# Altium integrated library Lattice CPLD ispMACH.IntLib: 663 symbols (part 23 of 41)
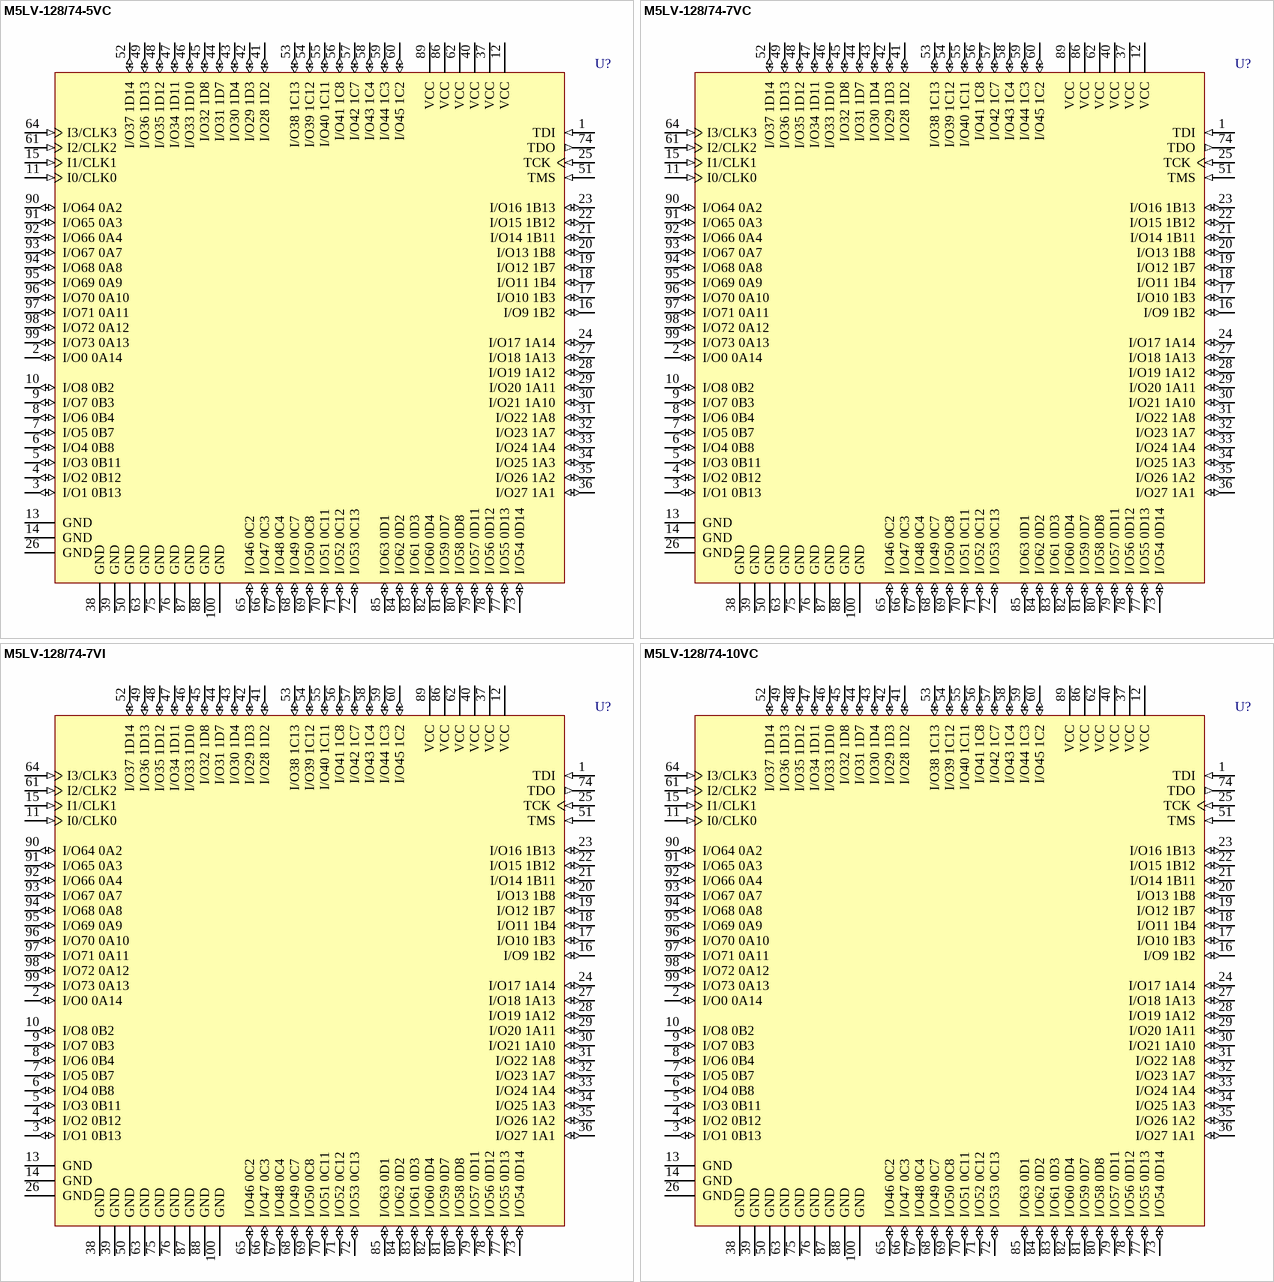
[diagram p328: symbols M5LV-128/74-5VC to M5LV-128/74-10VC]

## M5LV-128/74-7VI
designator U?
High-Density and High-I/O Complex PLD
footprint TQFP100_N (Thin QFP, 100-Leads, Body 14x14mm, Pitch 0.5mm, IPC Medium Density)
footprint TQFP100_L (Thin QFP, 100-Leads, Body 14x14mm, Pitch 0.5mm, IPC High Density)
footprint TQFP100_M (Thin QFP, 100-Leads, Body 14x14mm, Pitch 0.5mm, IPC Low Density)
3D model M5LV-TQFP100 (100-Pin Thin Quad Flat Pack (TQFP100))
pins: 1 TDI (in), 2 I/O0 0A14 (io), 3 I/O1 0B13 (io), 4 I/O2 0B12 (io), 5 I/O3 0B11 (io), 6 I/O4 0B8 (io), 7 I/O5 0B7 (io), 8 I/O6 0B4 (io), 9 I/O7 0B3 (io), 10 I/O8 0B2 (io), 11 I0/CLK0 (in), 12 VCC (power), 13 GND (power), 14 GND (power), 15 I1/CLK1 (in), 16 I/O9 1B2 (io), 17 I/O10 1B3 (io), 18 I/O11 1B4 (io), 19 I/O12 1B7 (io), 20 I/O13 1B8 (io), 21 I/O14 1B11 (io), 22 I/O15 1B12 (io), 23 I/O16 1B13 (io), 24 I/O17 1A14 (io), 25 TCK (in), 26 GND (power), 27 I/O18 1A13 (io), 28 I/O19 1A12 (io), 29 I/O20 1A11 (io), 30 I/O21 1A10 (io), 31 I/O22 1A8 (io), 32 I/O23 1A7 (io), 33 I/O24 1A4 (io), 34 I/O25 1A3 (io), 35 I/O26 1A2 (io), 36 I/O27 1A1 (io), 37 VCC (power), 38 GND (power), 39 GND (power), 40 VCC (power), 41 I/O28 1D2 (io), 42 I/O29 1D3 (io), 43 I/O30 1D4 (io), 44 I/O31 1D7 (io), 45 I/O32 1D8 (io), 46 I/O33 1D10 (io), 47 I/O34 1D11 (io), 48 I/O35 1D12 (io), 49 I/O36 1D13 (io), 50 GND (power), 51 TMS (in), 52 I/O37 1D14 (io), 53 I/O38 1C13 (io), 54 I/O39 1C12 (io), 55 I/O40 1C11 (io), 56 I/O41 1C8 (io), 57 I/O42 1C7 (io), 58 I/O43 1C4 (io), 59 I/O44 1C3 (io), 60 I/O45 1C2 (io), 61 I2/CLK2 (in), 62 VCC (power), 63 GND (power), 64 I3/CLK3 (in), 65 I/O46 0C2 (io), 66 I/O47 0C3 (io), 67 I/O48 0C4 (io), 68 I/O49 0C7 (io), 69 I/O50 0C8 (io), 70 I/O51 0C11 (io), 71 I/O52 0C12 (io), 72 I/O53 0C13 (io), 73 I/O54 0D14 (io), 74 TDO (out), 75 GND (power), 76 GND (power), 77 I/O55 0D13 (io), 78 I/O56 0D12 (io), 79 I/O57 0D11 (io), 80 I/O58 0D8 (io), 81 I/O59 0D7 (io), 82 I/O60 0D4 (io), 83 I/O61 0D3 (io), 84 I/O62 0D2 (io), 85 I/O63 0D1 (io), 86 VCC (power), 87 GND (power), 88 GND (power), 89 VCC (power), 90 I/O64 0A2 (io), 91 I/O65 0A3 (io), 92 I/O66 0A4 (io), 93 I/O67 0A7 (io), 94 I/O68 0A8 (io), 95 I/O69 0A9 (io), 96 I/O70 0A10 (io), 97 I/O71 0A11 (io), 98 I/O72 0A12 (io), 99 I/O73 0A13 (io), 100 GND (power)

## M5LV-128/74-10VC
designator U?
High-Density and High-I/O Complex PLD
footprint TQFP100_N (Thin QFP, 100-Leads, Body 14x14mm, Pitch 0.5mm, IPC Medium Density)
footprint TQFP100_L (Thin QFP, 100-Leads, Body 14x14mm, Pitch 0.5mm, IPC High Density)
footprint TQFP100_M (Thin QFP, 100-Leads, Body 14x14mm, Pitch 0.5mm, IPC Low Density)
3D model M5LV-TQFP100 (100-Pin Thin Quad Flat Pack (TQFP100))
pins: 1 TDI (in), 2 I/O0 0A14 (io), 3 I/O1 0B13 (io), 4 I/O2 0B12 (io), 5 I/O3 0B11 (io), 6 I/O4 0B8 (io), 7 I/O5 0B7 (io), 8 I/O6 0B4 (io), 9 I/O7 0B3 (io), 10 I/O8 0B2 (io), 11 I0/CLK0 (in), 12 VCC (power), 13 GND (power), 14 GND (power), 15 I1/CLK1 (in), 16 I/O9 1B2 (io), 17 I/O10 1B3 (io), 18 I/O11 1B4 (io), 19 I/O12 1B7 (io), 20 I/O13 1B8 (io), 21 I/O14 1B11 (io), 22 I/O15 1B12 (io), 23 I/O16 1B13 (io), 24 I/O17 1A14 (io), 25 TCK (in), 26 GND (power), 27 I/O18 1A13 (io), 28 I/O19 1A12 (io), 29 I/O20 1A11 (io), 30 I/O21 1A10 (io), 31 I/O22 1A8 (io), 32 I/O23 1A7 (io), 33 I/O24 1A4 (io), 34 I/O25 1A3 (io), 35 I/O26 1A2 (io), 36 I/O27 1A1 (io), 37 VCC (power), 38 GND (power), 39 GND (power), 40 VCC (power), 41 I/O28 1D2 (io), 42 I/O29 1D3 (io), 43 I/O30 1D4 (io), 44 I/O31 1D7 (io), 45 I/O32 1D8 (io), 46 I/O33 1D10 (io), 47 I/O34 1D11 (io), 48 I/O35 1D12 (io), 49 I/O36 1D13 (io), 50 GND (power), 51 TMS (in), 52 I/O37 1D14 (io), 53 I/O38 1C13 (io), 54 I/O39 1C12 (io), 55 I/O40 1C11 (io), 56 I/O41 1C8 (io), 57 I/O42 1C7 (io), 58 I/O43 1C4 (io), 59 I/O44 1C3 (io), 60 I/O45 1C2 (io), 61 I2/CLK2 (in), 62 VCC (power), 63 GND (power), 64 I3/CLK3 (in), 65 I/O46 0C2 (io), 66 I/O47 0C3 (io), 67 I/O48 0C4 (io), 68 I/O49 0C7 (io), 69 I/O50 0C8 (io), 70 I/O51 0C11 (io), 71 I/O52 0C12 (io), 72 I/O53 0C13 (io), 73 I/O54 0D14 (io), 74 TDO (out), 75 GND (power), 76 GND (power), 77 I/O55 0D13 (io), 78 I/O56 0D12 (io), 79 I/O57 0D11 (io), 80 I/O58 0D8 (io), 81 I/O59 0D7 (io), 82 I/O60 0D4 (io), 83 I/O61 0D3 (io), 84 I/O62 0D2 (io), 85 I/O63 0D1 (io), 86 VCC (power), 87 GND (power), 88 GND (power), 89 VCC (power), 90 I/O64 0A2 (io), 91 I/O65 0A3 (io), 92 I/O66 0A4 (io), 93 I/O67 0A7 (io), 94 I/O68 0A8 (io), 95 I/O69 0A9 (io), 96 I/O70 0A10 (io), 97 I/O71 0A11 (io), 98 I/O72 0A12 (io), 99 I/O73 0A13 (io), 100 GND (power)

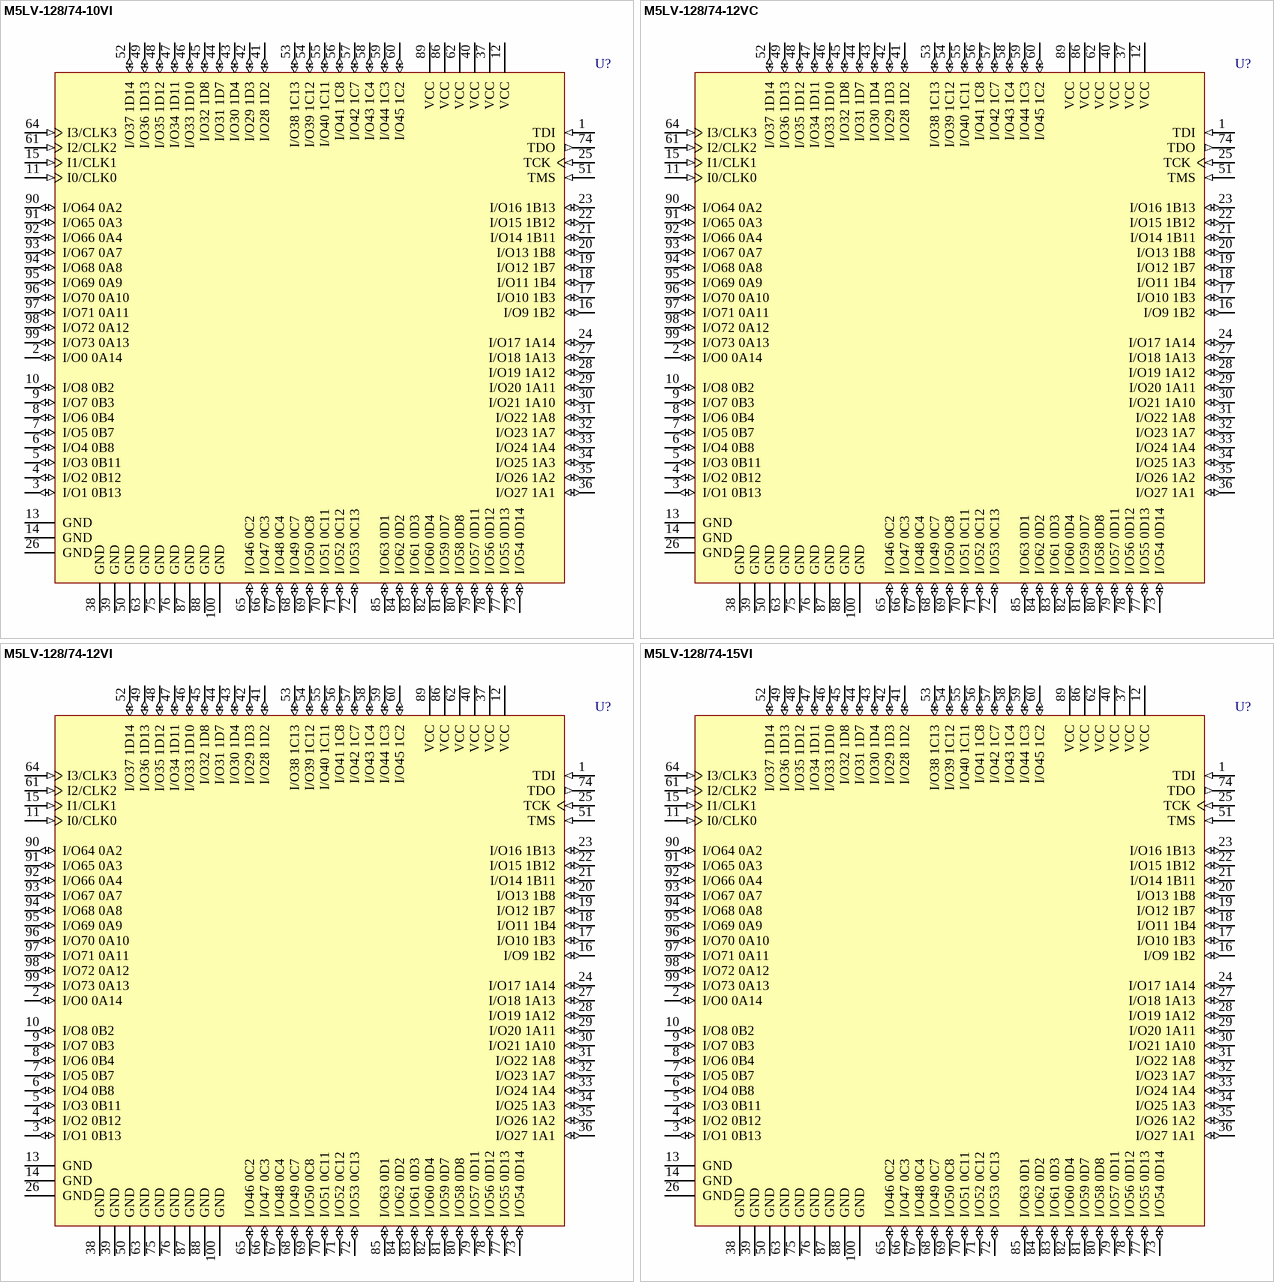
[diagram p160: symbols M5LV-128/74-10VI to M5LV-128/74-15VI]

## M5LV-128/74-10VI
designator U?
High-Density and High-I/O Complex PLD
footprint TQFP100_N (Thin QFP, 100-Leads, Body 14x14mm, Pitch 0.5mm, IPC Medium Density)
footprint TQFP100_L (Thin QFP, 100-Leads, Body 14x14mm, Pitch 0.5mm, IPC High Density)
footprint TQFP100_M (Thin QFP, 100-Leads, Body 14x14mm, Pitch 0.5mm, IPC Low Density)
3D model M5LV-TQFP100 (100-Pin Thin Quad Flat Pack (TQFP100))
pins: 1 TDI (in), 2 I/O0 0A14 (io), 3 I/O1 0B13 (io), 4 I/O2 0B12 (io), 5 I/O3 0B11 (io), 6 I/O4 0B8 (io), 7 I/O5 0B7 (io), 8 I/O6 0B4 (io), 9 I/O7 0B3 (io), 10 I/O8 0B2 (io), 11 I0/CLK0 (in), 12 VCC (power), 13 GND (power), 14 GND (power), 15 I1/CLK1 (in), 16 I/O9 1B2 (io), 17 I/O10 1B3 (io), 18 I/O11 1B4 (io), 19 I/O12 1B7 (io), 20 I/O13 1B8 (io), 21 I/O14 1B11 (io), 22 I/O15 1B12 (io), 23 I/O16 1B13 (io), 24 I/O17 1A14 (io), 25 TCK (in), 26 GND (power), 27 I/O18 1A13 (io), 28 I/O19 1A12 (io), 29 I/O20 1A11 (io), 30 I/O21 1A10 (io), 31 I/O22 1A8 (io), 32 I/O23 1A7 (io), 33 I/O24 1A4 (io), 34 I/O25 1A3 (io), 35 I/O26 1A2 (io), 36 I/O27 1A1 (io), 37 VCC (power), 38 GND (power), 39 GND (power), 40 VCC (power), 41 I/O28 1D2 (io), 42 I/O29 1D3 (io), 43 I/O30 1D4 (io), 44 I/O31 1D7 (io), 45 I/O32 1D8 (io), 46 I/O33 1D10 (io), 47 I/O34 1D11 (io), 48 I/O35 1D12 (io), 49 I/O36 1D13 (io), 50 GND (power), 51 TMS (in), 52 I/O37 1D14 (io), 53 I/O38 1C13 (io), 54 I/O39 1C12 (io), 55 I/O40 1C11 (io), 56 I/O41 1C8 (io), 57 I/O42 1C7 (io), 58 I/O43 1C4 (io), 59 I/O44 1C3 (io), 60 I/O45 1C2 (io), 61 I2/CLK2 (in), 62 VCC (power), 63 GND (power), 64 I3/CLK3 (in), 65 I/O46 0C2 (io), 66 I/O47 0C3 (io), 67 I/O48 0C4 (io), 68 I/O49 0C7 (io), 69 I/O50 0C8 (io), 70 I/O51 0C11 (io), 71 I/O52 0C12 (io), 72 I/O53 0C13 (io), 73 I/O54 0D14 (io), 74 TDO (out), 75 GND (power), 76 GND (power), 77 I/O55 0D13 (io), 78 I/O56 0D12 (io), 79 I/O57 0D11 (io), 80 I/O58 0D8 (io), 81 I/O59 0D7 (io), 82 I/O60 0D4 (io), 83 I/O61 0D3 (io), 84 I/O62 0D2 (io), 85 I/O63 0D1 (io), 86 VCC (power), 87 GND (power), 88 GND (power), 89 VCC (power), 90 I/O64 0A2 (io), 91 I/O65 0A3 (io), 92 I/O66 0A4 (io), 93 I/O67 0A7 (io), 94 I/O68 0A8 (io), 95 I/O69 0A9 (io), 96 I/O70 0A10 (io), 97 I/O71 0A11 (io), 98 I/O72 0A12 (io), 99 I/O73 0A13 (io), 100 GND (power)

## M5LV-128/74-12VC
designator U?
High-Density and High-I/O Complex PLD
footprint TQFP100_N (Thin QFP, 100-Leads, Body 14x14mm, Pitch 0.5mm, IPC Medium Density)
footprint TQFP100_L (Thin QFP, 100-Leads, Body 14x14mm, Pitch 0.5mm, IPC High Density)
footprint TQFP100_M (Thin QFP, 100-Leads, Body 14x14mm, Pitch 0.5mm, IPC Low Density)
3D model M5LV-TQFP100 (100-Pin Thin Quad Flat Pack (TQFP100))
pins: 1 TDI (in), 2 I/O0 0A14 (io), 3 I/O1 0B13 (io), 4 I/O2 0B12 (io), 5 I/O3 0B11 (io), 6 I/O4 0B8 (io), 7 I/O5 0B7 (io), 8 I/O6 0B4 (io), 9 I/O7 0B3 (io), 10 I/O8 0B2 (io), 11 I0/CLK0 (in), 12 VCC (power), 13 GND (power), 14 GND (power), 15 I1/CLK1 (in), 16 I/O9 1B2 (io), 17 I/O10 1B3 (io), 18 I/O11 1B4 (io), 19 I/O12 1B7 (io), 20 I/O13 1B8 (io), 21 I/O14 1B11 (io), 22 I/O15 1B12 (io), 23 I/O16 1B13 (io), 24 I/O17 1A14 (io), 25 TCK (in), 26 GND (power), 27 I/O18 1A13 (io), 28 I/O19 1A12 (io), 29 I/O20 1A11 (io), 30 I/O21 1A10 (io), 31 I/O22 1A8 (io), 32 I/O23 1A7 (io), 33 I/O24 1A4 (io), 34 I/O25 1A3 (io), 35 I/O26 1A2 (io), 36 I/O27 1A1 (io), 37 VCC (power), 38 GND (power), 39 GND (power), 40 VCC (power), 41 I/O28 1D2 (io), 42 I/O29 1D3 (io), 43 I/O30 1D4 (io), 44 I/O31 1D7 (io), 45 I/O32 1D8 (io), 46 I/O33 1D10 (io), 47 I/O34 1D11 (io), 48 I/O35 1D12 (io), 49 I/O36 1D13 (io), 50 GND (power), 51 TMS (in), 52 I/O37 1D14 (io), 53 I/O38 1C13 (io), 54 I/O39 1C12 (io), 55 I/O40 1C11 (io), 56 I/O41 1C8 (io), 57 I/O42 1C7 (io), 58 I/O43 1C4 (io), 59 I/O44 1C3 (io), 60 I/O45 1C2 (io), 61 I2/CLK2 (in), 62 VCC (power), 63 GND (power), 64 I3/CLK3 (in), 65 I/O46 0C2 (io), 66 I/O47 0C3 (io), 67 I/O48 0C4 (io), 68 I/O49 0C7 (io), 69 I/O50 0C8 (io), 70 I/O51 0C11 (io), 71 I/O52 0C12 (io), 72 I/O53 0C13 (io), 73 I/O54 0D14 (io), 74 TDO (out), 75 GND (power), 76 GND (power), 77 I/O55 0D13 (io), 78 I/O56 0D12 (io), 79 I/O57 0D11 (io), 80 I/O58 0D8 (io), 81 I/O59 0D7 (io), 82 I/O60 0D4 (io), 83 I/O61 0D3 (io), 84 I/O62 0D2 (io), 85 I/O63 0D1 (io), 86 VCC (power), 87 GND (power), 88 GND (power), 89 VCC (power), 90 I/O64 0A2 (io), 91 I/O65 0A3 (io), 92 I/O66 0A4 (io), 93 I/O67 0A7 (io), 94 I/O68 0A8 (io), 95 I/O69 0A9 (io), 96 I/O70 0A10 (io), 97 I/O71 0A11 (io), 98 I/O72 0A12 (io), 99 I/O73 0A13 (io), 100 GND (power)

## M5LV-128/74-12VI
designator U?
High-Density and High-I/O Complex PLD
footprint TQFP100_N (Thin QFP, 100-Leads, Body 14x14mm, Pitch 0.5mm, IPC Medium Density)
footprint TQFP100_L (Thin QFP, 100-Leads, Body 14x14mm, Pitch 0.5mm, IPC High Density)
footprint TQFP100_M (Thin QFP, 100-Leads, Body 14x14mm, Pitch 0.5mm, IPC Low Density)
3D model M5LV-TQFP100 (100-Pin Thin Quad Flat Pack (TQFP100))
pins: 1 TDI (in), 2 I/O0 0A14 (io), 3 I/O1 0B13 (io), 4 I/O2 0B12 (io), 5 I/O3 0B11 (io), 6 I/O4 0B8 (io), 7 I/O5 0B7 (io), 8 I/O6 0B4 (io), 9 I/O7 0B3 (io), 10 I/O8 0B2 (io), 11 I0/CLK0 (in), 12 VCC (power), 13 GND (power), 14 GND (power), 15 I1/CLK1 (in), 16 I/O9 1B2 (io), 17 I/O10 1B3 (io), 18 I/O11 1B4 (io), 19 I/O12 1B7 (io), 20 I/O13 1B8 (io), 21 I/O14 1B11 (io), 22 I/O15 1B12 (io), 23 I/O16 1B13 (io), 24 I/O17 1A14 (io), 25 TCK (in), 26 GND (power), 27 I/O18 1A13 (io), 28 I/O19 1A12 (io), 29 I/O20 1A11 (io), 30 I/O21 1A10 (io), 31 I/O22 1A8 (io), 32 I/O23 1A7 (io), 33 I/O24 1A4 (io), 34 I/O25 1A3 (io), 35 I/O26 1A2 (io), 36 I/O27 1A1 (io), 37 VCC (power), 38 GND (power), 39 GND (power), 40 VCC (power), 41 I/O28 1D2 (io), 42 I/O29 1D3 (io), 43 I/O30 1D4 (io), 44 I/O31 1D7 (io), 45 I/O32 1D8 (io), 46 I/O33 1D10 (io), 47 I/O34 1D11 (io), 48 I/O35 1D12 (io), 49 I/O36 1D13 (io), 50 GND (power), 51 TMS (in), 52 I/O37 1D14 (io), 53 I/O38 1C13 (io), 54 I/O39 1C12 (io), 55 I/O40 1C11 (io), 56 I/O41 1C8 (io), 57 I/O42 1C7 (io), 58 I/O43 1C4 (io), 59 I/O44 1C3 (io), 60 I/O45 1C2 (io), 61 I2/CLK2 (in), 62 VCC (power), 63 GND (power), 64 I3/CLK3 (in), 65 I/O46 0C2 (io), 66 I/O47 0C3 (io), 67 I/O48 0C4 (io), 68 I/O49 0C7 (io), 69 I/O50 0C8 (io), 70 I/O51 0C11 (io), 71 I/O52 0C12 (io), 72 I/O53 0C13 (io), 73 I/O54 0D14 (io), 74 TDO (out), 75 GND (power), 76 GND (power), 77 I/O55 0D13 (io), 78 I/O56 0D12 (io), 79 I/O57 0D11 (io), 80 I/O58 0D8 (io), 81 I/O59 0D7 (io), 82 I/O60 0D4 (io), 83 I/O61 0D3 (io), 84 I/O62 0D2 (io), 85 I/O63 0D1 (io), 86 VCC (power), 87 GND (power), 88 GND (power), 89 VCC (power), 90 I/O64 0A2 (io), 91 I/O65 0A3 (io), 92 I/O66 0A4 (io), 93 I/O67 0A7 (io), 94 I/O68 0A8 (io), 95 I/O69 0A9 (io), 96 I/O70 0A10 (io), 97 I/O71 0A11 (io), 98 I/O72 0A12 (io), 99 I/O73 0A13 (io), 100 GND (power)

## M5LV-128/74-15VI
designator U?
High-Density and High-I/O Complex PLD
footprint TQFP100_N (Thin QFP, 100-Leads, Body 14x14mm, Pitch 0.5mm, IPC Medium Density)
footprint TQFP100_L (Thin QFP, 100-Leads, Body 14x14mm, Pitch 0.5mm, IPC High Density)
footprint TQFP100_M (Thin QFP, 100-Leads, Body 14x14mm, Pitch 0.5mm, IPC Low Density)
3D model M5LV-TQFP100 (100-Pin Thin Quad Flat Pack (TQFP100))
pins: 1 TDI (in), 2 I/O0 0A14 (io), 3 I/O1 0B13 (io), 4 I/O2 0B12 (io), 5 I/O3 0B11 (io), 6 I/O4 0B8 (io), 7 I/O5 0B7 (io), 8 I/O6 0B4 (io), 9 I/O7 0B3 (io), 10 I/O8 0B2 (io), 11 I0/CLK0 (in), 12 VCC (power), 13 GND (power), 14 GND (power), 15 I1/CLK1 (in), 16 I/O9 1B2 (io), 17 I/O10 1B3 (io), 18 I/O11 1B4 (io), 19 I/O12 1B7 (io), 20 I/O13 1B8 (io), 21 I/O14 1B11 (io), 22 I/O15 1B12 (io), 23 I/O16 1B13 (io), 24 I/O17 1A14 (io), 25 TCK (in), 26 GND (power), 27 I/O18 1A13 (io), 28 I/O19 1A12 (io), 29 I/O20 1A11 (io), 30 I/O21 1A10 (io), 31 I/O22 1A8 (io), 32 I/O23 1A7 (io), 33 I/O24 1A4 (io), 34 I/O25 1A3 (io), 35 I/O26 1A2 (io), 36 I/O27 1A1 (io), 37 VCC (power), 38 GND (power), 39 GND (power), 40 VCC (power), 41 I/O28 1D2 (io), 42 I/O29 1D3 (io), 43 I/O30 1D4 (io), 44 I/O31 1D7 (io), 45 I/O32 1D8 (io), 46 I/O33 1D10 (io), 47 I/O34 1D11 (io), 48 I/O35 1D12 (io), 49 I/O36 1D13 (io), 50 GND (power), 51 TMS (in), 52 I/O37 1D14 (io), 53 I/O38 1C13 (io), 54 I/O39 1C12 (io), 55 I/O40 1C11 (io), 56 I/O41 1C8 (io), 57 I/O42 1C7 (io), 58 I/O43 1C4 (io), 59 I/O44 1C3 (io), 60 I/O45 1C2 (io), 61 I2/CLK2 (in), 62 VCC (power), 63 GND (power), 64 I3/CLK3 (in), 65 I/O46 0C2 (io), 66 I/O47 0C3 (io), 67 I/O48 0C4 (io), 68 I/O49 0C7 (io), 69 I/O50 0C8 (io), 70 I/O51 0C11 (io), 71 I/O52 0C12 (io), 72 I/O53 0C13 (io), 73 I/O54 0D14 (io), 74 TDO (out), 75 GND (power), 76 GND (power), 77 I/O55 0D13 (io), 78 I/O56 0D12 (io), 79 I/O57 0D11 (io), 80 I/O58 0D8 (io), 81 I/O59 0D7 (io), 82 I/O60 0D4 (io), 83 I/O61 0D3 (io), 84 I/O62 0D2 (io), 85 I/O63 0D1 (io), 86 VCC (power), 87 GND (power), 88 GND (power), 89 VCC (power), 90 I/O64 0A2 (io), 91 I/O65 0A3 (io), 92 I/O66 0A4 (io), 93 I/O67 0A7 (io), 94 I/O68 0A8 (io), 95 I/O69 0A9 (io), 96 I/O70 0A10 (io), 97 I/O71 0A11 (io), 98 I/O72 0A12 (io), 99 I/O73 0A13 (io), 100 GND (power)

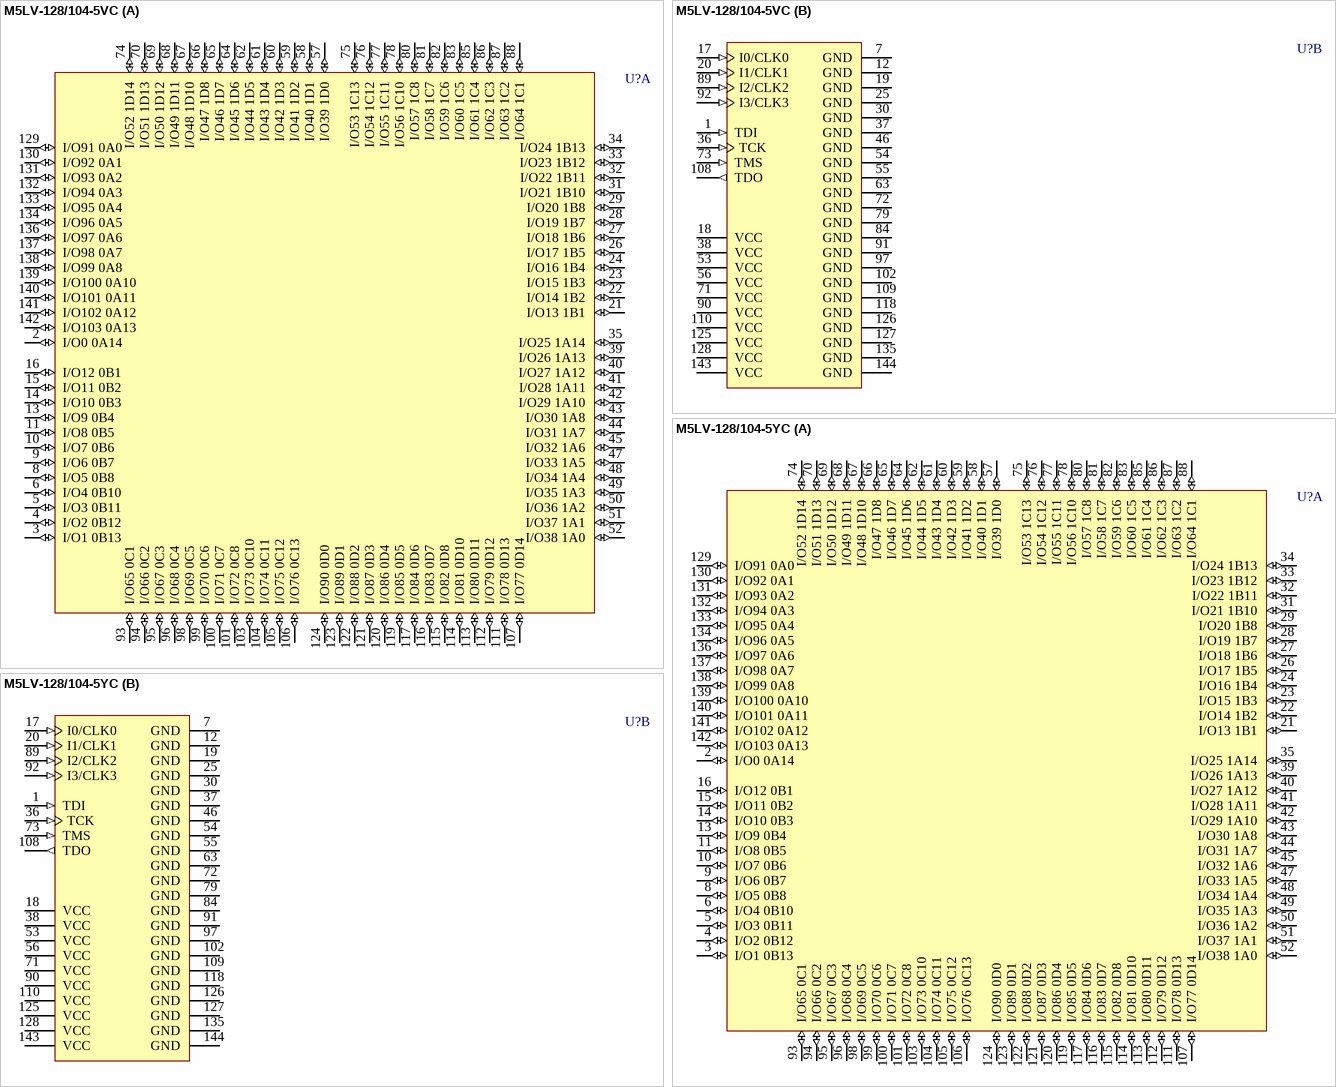
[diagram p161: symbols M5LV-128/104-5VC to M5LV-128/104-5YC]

## M5LV-128/104-5VC
designator U?
High-Density and High-I/O Complex PLD
footprint TQFP144_N (Thin QFP, 144-Leads, Body 20x20mm, Pitch 0.5mm, IPC Medium Density)
footprint TQFP144_L (Thin QFP, 144-Leads, Body 20x20mm, Pitch 0.5mm, IPC High Density)
footprint TQFP144_M (Thin QFP, 144-Leads, Body 20x20mm, Pitch 0.5mm, IPC Low Density)
3D model M5LV-TQFP144 (144-Pin Thin Quad Flat Pack (TQFP144))
part A pins: 2 I/O0 0A14 (io), 3 I/O1 0B13 (io), 4 I/O2 0B12 (io), 5 I/O3 0B11 (io), 6 I/O4 0B10 (io), 8 I/O5 0B8 (io), 9 I/O6 0B7 (io), 10 I/O7 0B6 (io), 11 I/O8 0B5 (io), 13 I/O9 0B4 (io), 14 I/O10 0B3 (io), 15 I/O11 0B2 (io), 16 I/O12 0B1 (io), 21 I/O13 1B1 (io), 22 I/O14 1B2 (io), 23 I/O15 1B3 (io), 24 I/O16 1B4 (io), 26 I/O17 1B5 (io), 27 I/O18 1B6 (io), 28 I/O19 1B7 (io), 29 I/O20 1B8 (io), 31 I/O21 1B10 (io), 32 I/O22 1B11 (io), 33 I/O23 1B12 (io), 34 I/O24 1B13 (io), 35 I/O25 1A14 (io), 39 I/O26 1A13 (io), 40 I/O27 1A12 (io), 41 I/O28 1A11 (io), 42 I/O29 1A10 (io), 43 I/O30 1A8 (io), 44 I/O31 1A7 (io), 45 I/O32 1A6 (io), 47 I/O33 1A5 (io), 48 I/O34 1A4 (io), 49 I/O35 1A3 (io), 50 I/O36 1A2 (io), 51 I/O37 1A1 (io), 52 I/O38 1A0 (io), 57 I/O39 1D0 (io), 58 I/O40 1D1 (io), 59 I/O41 1D2 (io), 60 I/O42 1D3 (io), 61 I/O43 1D4 (io), 62 I/O44 1D5 (io), 64 I/O45 1D6 (io), 65 I/O46 1D7 (io), 66 I/O47 1D8 (io), 67 I/O48 1D10 (io), 68 I/O49 1D11 (io), 69 I/O50 1D12 (io), 70 I/O51 1D13 (io), 74 I/O52 1D14 (io), 75 I/O53 1C13 (io), 76 I/O54 1C12 (io), 77 I/O55 1C11 (io), 78 I/O56 1C10 (io), 80 I/O57 1C8 (io), 81 I/O58 1C7 (io), 82 I/O59 1C6 (io), 83 I/O60 1C5 (io), 85 I/O61 1C4 (io), 86 I/O62 1C3 (io), 87 I/O63 1C2 (io), 88 I/O64 1C1 (io), 93 I/O65 0C1 (io), 94 I/O66 0C2 (io), 95 I/O67 0C3 (io), 96 I/O68 0C4 (io), 98 I/O69 0C5 (io), 99 I/O70 0C6 (io), 100 I/O71 0C7 (io), 101 I/O72 0C8 (io), 103 I/O73 0C10 (io), 104 I/O74 0C11 (io), 105 I/O75 0C12 (io), 106 I/O76 0C13 (io), 107 I/O77 0D14 (io), 111 I/O78 0D13 (io), 112 I/O79 0D12 (io), 113 I/O80 0D11 (io), 114 I/O81 0D10 (io), 115 I/O82 0D8 (io), 116 I/O83 0D7 (io), 117 I/O84 0D6 (io), 119 I/O85 0D5 (io), 120 I/O86 0D4 (io), 121 I/O87 0D3 (io), 122 I/O88 0D2 (io), 123 I/O89 0D1 (io), 124 I/O90 0D0 (io), 129 I/O91 0A0 (io), 130 I/O92 0A1 (io), 131 I/O93 0A2 (io), 132 I/O94 0A3 (io), 133 I/O95 0A4 (io), 134 I/O96 0A5 (io), 136 I/O97 0A6 (io), 137 I/O98 0A7 (io), 138 I/O99 0A8 (io), 139 I/O100 0A10 (io), 140 I/O101 0A11 (io), 141 I/O102 0A12 (io), 142 I/O103 0A13 (io)
part B pins: 1 TDI (in), 7 GND (power), 12 GND (power), 17 I0/CLK0 (in), 18 VCC (power), 19 GND (power), 20 I1/CLK1 (in), 25 GND (power), 30 GND (power), 36 TCK (in), 37 GND (power), 38 VCC (power), 46 GND (power), 53 VCC (power), 54 GND (power), 55 GND (power), 56 VCC (power), 63 GND (power), 71 VCC (power), 72 GND (power), 73 TMS (in), 79 GND (power), 84 GND (power), 89 I2/CLK2 (in), 90 VCC (power), 91 GND (power), 92 I3/CLK3 (in), 97 GND (power), 102 GND (power), 108 TDO (out), 109 GND (power), 110 VCC (power), 118 GND (power), 125 VCC (power), 126 GND (power), 127 GND (power), 128 VCC (power), 135 GND (power), 143 VCC (power), 144 GND (power)

## M5LV-128/104-5YC
designator U?
High-Density and High-I/O Complex PLD
footprint PQFP144_N (QFP, 144-Leads, Body 28 x 28mm, Pitch 0.65mm, IPC Medium Density)
footprint PQFP144_L (QFP, 144-Leads, Body 28 x 28mm, Pitch 0.65mm, IPC High Density)
footprint PQFP144_M (QFP, 144-Leads, Body 28 x 28mm, Pitch 0.65mm, IPC Low Density)
3D model M5LV-PQFP144 (144-Pin Quad Flat Pack 0.65 mm Pitch)
part A pins: 2 I/O0 0A14 (io), 3 I/O1 0B13 (io), 4 I/O2 0B12 (io), 5 I/O3 0B11 (io), 6 I/O4 0B10 (io), 8 I/O5 0B8 (io), 9 I/O6 0B7 (io), 10 I/O7 0B6 (io), 11 I/O8 0B5 (io), 13 I/O9 0B4 (io), 14 I/O10 0B3 (io), 15 I/O11 0B2 (io), 16 I/O12 0B1 (io), 21 I/O13 1B1 (io), 22 I/O14 1B2 (io), 23 I/O15 1B3 (io), 24 I/O16 1B4 (io), 26 I/O17 1B5 (io), 27 I/O18 1B6 (io), 28 I/O19 1B7 (io), 29 I/O20 1B8 (io), 31 I/O21 1B10 (io), 32 I/O22 1B11 (io), 33 I/O23 1B12 (io), 34 I/O24 1B13 (io), 35 I/O25 1A14 (io), 39 I/O26 1A13 (io), 40 I/O27 1A12 (io), 41 I/O28 1A11 (io), 42 I/O29 1A10 (io), 43 I/O30 1A8 (io), 44 I/O31 1A7 (io), 45 I/O32 1A6 (io), 47 I/O33 1A5 (io), 48 I/O34 1A4 (io), 49 I/O35 1A3 (io), 50 I/O36 1A2 (io), 51 I/O37 1A1 (io), 52 I/O38 1A0 (io), 57 I/O39 1D0 (io), 58 I/O40 1D1 (io), 59 I/O41 1D2 (io), 60 I/O42 1D3 (io), 61 I/O43 1D4 (io), 62 I/O44 1D5 (io), 64 I/O45 1D6 (io), 65 I/O46 1D7 (io), 66 I/O47 1D8 (io), 67 I/O48 1D10 (io), 68 I/O49 1D11 (io), 69 I/O50 1D12 (io), 70 I/O51 1D13 (io), 74 I/O52 1D14 (io), 75 I/O53 1C13 (io), 76 I/O54 1C12 (io), 77 I/O55 1C11 (io), 78 I/O56 1C10 (io), 80 I/O57 1C8 (io), 81 I/O58 1C7 (io), 82 I/O59 1C6 (io), 83 I/O60 1C5 (io), 85 I/O61 1C4 (io), 86 I/O62 1C3 (io), 87 I/O63 1C2 (io), 88 I/O64 1C1 (io), 93 I/O65 0C1 (io), 94 I/O66 0C2 (io), 95 I/O67 0C3 (io), 96 I/O68 0C4 (io), 98 I/O69 0C5 (io), 99 I/O70 0C6 (io), 100 I/O71 0C7 (io), 101 I/O72 0C8 (io), 103 I/O73 0C10 (io), 104 I/O74 0C11 (io), 105 I/O75 0C12 (io), 106 I/O76 0C13 (io), 107 I/O77 0D14 (io), 111 I/O78 0D13 (io), 112 I/O79 0D12 (io), 113 I/O80 0D11 (io), 114 I/O81 0D10 (io), 115 I/O82 0D8 (io), 116 I/O83 0D7 (io), 117 I/O84 0D6 (io), 119 I/O85 0D5 (io), 120 I/O86 0D4 (io), 121 I/O87 0D3 (io), 122 I/O88 0D2 (io), 123 I/O89 0D1 (io), 124 I/O90 0D0 (io), 129 I/O91 0A0 (io), 130 I/O92 0A1 (io), 131 I/O93 0A2 (io), 132 I/O94 0A3 (io), 133 I/O95 0A4 (io), 134 I/O96 0A5 (io), 136 I/O97 0A6 (io), 137 I/O98 0A7 (io), 138 I/O99 0A8 (io), 139 I/O100 0A10 (io), 140 I/O101 0A11 (io), 141 I/O102 0A12 (io), 142 I/O103 0A13 (io)
part B pins: 1 TDI (in), 7 GND (power), 12 GND (power), 17 I0/CLK0 (in), 18 VCC (power), 19 GND (power), 20 I1/CLK1 (in), 25 GND (power), 30 GND (power), 36 TCK (in), 37 GND (power), 38 VCC (power), 46 GND (power), 53 VCC (power), 54 GND (power), 55 GND (power), 56 VCC (power), 63 GND (power), 71 VCC (power), 72 GND (power), 73 TMS (in), 79 GND (power), 84 GND (power), 89 I2/CLK2 (in), 90 VCC (power), 91 GND (power), 92 I3/CLK3 (in), 97 GND (power), 102 GND (power), 108 TDO (out), 109 GND (power), 110 VCC (power), 118 GND (power), 125 VCC (power), 126 GND (power), 127 GND (power), 128 VCC (power), 135 GND (power), 143 VCC (power), 144 GND (power)

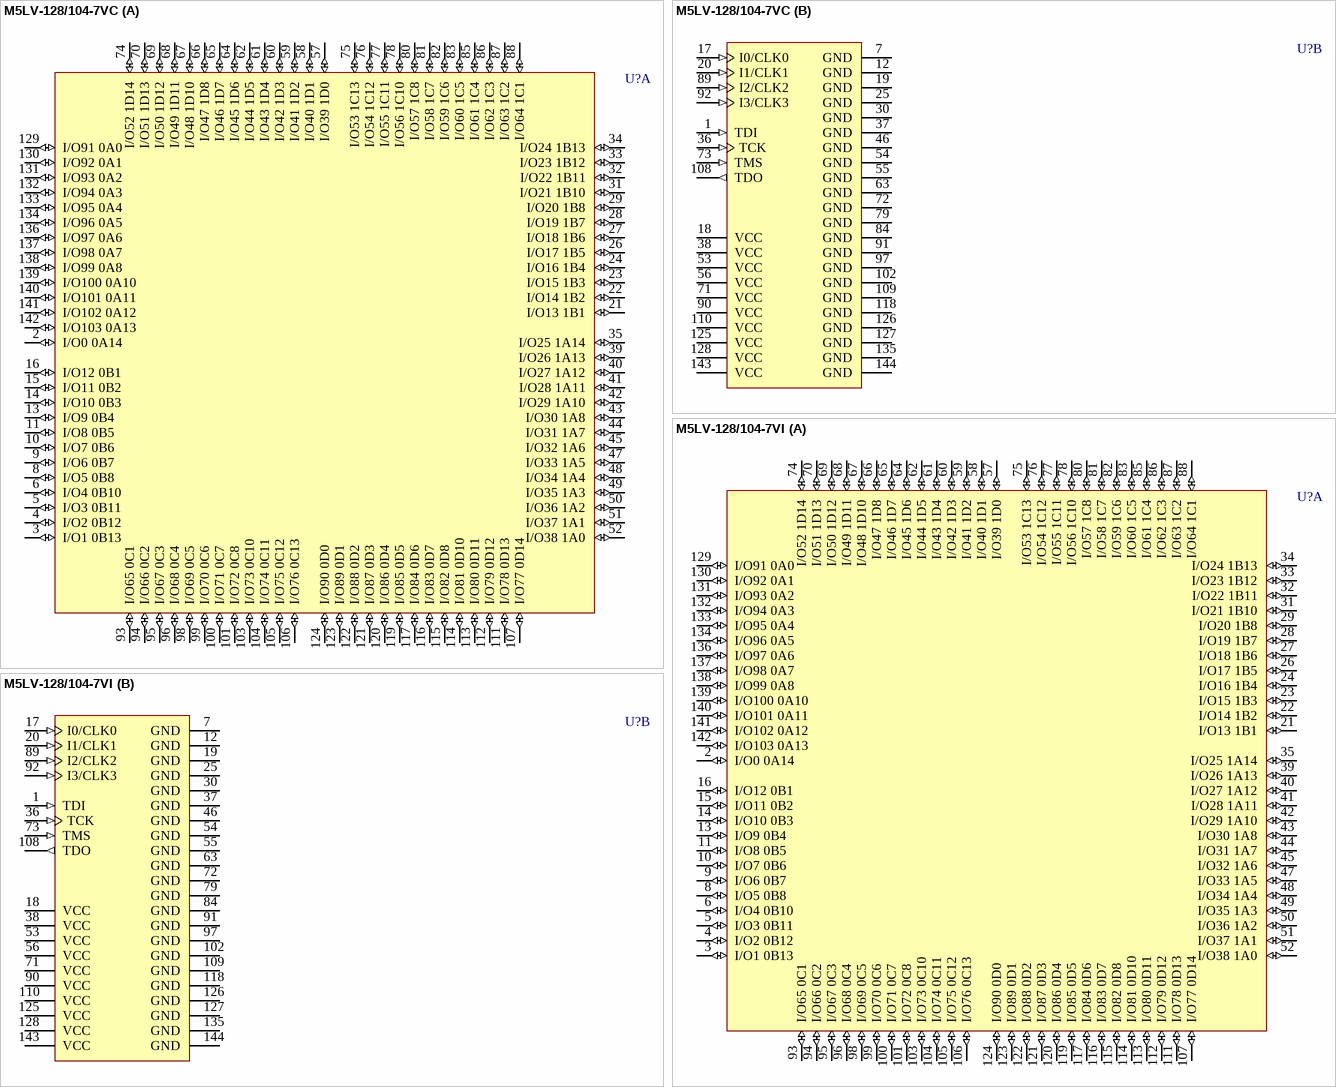
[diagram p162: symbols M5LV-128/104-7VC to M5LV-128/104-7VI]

## M5LV-128/104-7VC
designator U?
High-Density and High-I/O Complex PLD
footprint TQFP144_N (Thin QFP, 144-Leads, Body 20x20mm, Pitch 0.5mm, IPC Medium Density)
footprint TQFP144_L (Thin QFP, 144-Leads, Body 20x20mm, Pitch 0.5mm, IPC High Density)
footprint TQFP144_M (Thin QFP, 144-Leads, Body 20x20mm, Pitch 0.5mm, IPC Low Density)
3D model M5LV-TQFP144 (144-Pin Thin Quad Flat Pack (TQFP144))
part A pins: 2 I/O0 0A14 (io), 3 I/O1 0B13 (io), 4 I/O2 0B12 (io), 5 I/O3 0B11 (io), 6 I/O4 0B10 (io), 8 I/O5 0B8 (io), 9 I/O6 0B7 (io), 10 I/O7 0B6 (io), 11 I/O8 0B5 (io), 13 I/O9 0B4 (io), 14 I/O10 0B3 (io), 15 I/O11 0B2 (io), 16 I/O12 0B1 (io), 21 I/O13 1B1 (io), 22 I/O14 1B2 (io), 23 I/O15 1B3 (io), 24 I/O16 1B4 (io), 26 I/O17 1B5 (io), 27 I/O18 1B6 (io), 28 I/O19 1B7 (io), 29 I/O20 1B8 (io), 31 I/O21 1B10 (io), 32 I/O22 1B11 (io), 33 I/O23 1B12 (io), 34 I/O24 1B13 (io), 35 I/O25 1A14 (io), 39 I/O26 1A13 (io), 40 I/O27 1A12 (io), 41 I/O28 1A11 (io), 42 I/O29 1A10 (io), 43 I/O30 1A8 (io), 44 I/O31 1A7 (io), 45 I/O32 1A6 (io), 47 I/O33 1A5 (io), 48 I/O34 1A4 (io), 49 I/O35 1A3 (io), 50 I/O36 1A2 (io), 51 I/O37 1A1 (io), 52 I/O38 1A0 (io), 57 I/O39 1D0 (io), 58 I/O40 1D1 (io), 59 I/O41 1D2 (io), 60 I/O42 1D3 (io), 61 I/O43 1D4 (io), 62 I/O44 1D5 (io), 64 I/O45 1D6 (io), 65 I/O46 1D7 (io), 66 I/O47 1D8 (io), 67 I/O48 1D10 (io), 68 I/O49 1D11 (io), 69 I/O50 1D12 (io), 70 I/O51 1D13 (io), 74 I/O52 1D14 (io), 75 I/O53 1C13 (io), 76 I/O54 1C12 (io), 77 I/O55 1C11 (io), 78 I/O56 1C10 (io), 80 I/O57 1C8 (io), 81 I/O58 1C7 (io), 82 I/O59 1C6 (io), 83 I/O60 1C5 (io), 85 I/O61 1C4 (io), 86 I/O62 1C3 (io), 87 I/O63 1C2 (io), 88 I/O64 1C1 (io), 93 I/O65 0C1 (io), 94 I/O66 0C2 (io), 95 I/O67 0C3 (io), 96 I/O68 0C4 (io), 98 I/O69 0C5 (io), 99 I/O70 0C6 (io), 100 I/O71 0C7 (io), 101 I/O72 0C8 (io), 103 I/O73 0C10 (io), 104 I/O74 0C11 (io), 105 I/O75 0C12 (io), 106 I/O76 0C13 (io), 107 I/O77 0D14 (io), 111 I/O78 0D13 (io), 112 I/O79 0D12 (io), 113 I/O80 0D11 (io), 114 I/O81 0D10 (io), 115 I/O82 0D8 (io), 116 I/O83 0D7 (io), 117 I/O84 0D6 (io), 119 I/O85 0D5 (io), 120 I/O86 0D4 (io), 121 I/O87 0D3 (io), 122 I/O88 0D2 (io), 123 I/O89 0D1 (io), 124 I/O90 0D0 (io), 129 I/O91 0A0 (io), 130 I/O92 0A1 (io), 131 I/O93 0A2 (io), 132 I/O94 0A3 (io), 133 I/O95 0A4 (io), 134 I/O96 0A5 (io), 136 I/O97 0A6 (io), 137 I/O98 0A7 (io), 138 I/O99 0A8 (io), 139 I/O100 0A10 (io), 140 I/O101 0A11 (io), 141 I/O102 0A12 (io), 142 I/O103 0A13 (io)
part B pins: 1 TDI (in), 7 GND (power), 12 GND (power), 17 I0/CLK0 (in), 18 VCC (power), 19 GND (power), 20 I1/CLK1 (in), 25 GND (power), 30 GND (power), 36 TCK (in), 37 GND (power), 38 VCC (power), 46 GND (power), 53 VCC (power), 54 GND (power), 55 GND (power), 56 VCC (power), 63 GND (power), 71 VCC (power), 72 GND (power), 73 TMS (in), 79 GND (power), 84 GND (power), 89 I2/CLK2 (in), 90 VCC (power), 91 GND (power), 92 I3/CLK3 (in), 97 GND (power), 102 GND (power), 108 TDO (out), 109 GND (power), 110 VCC (power), 118 GND (power), 125 VCC (power), 126 GND (power), 127 GND (power), 128 VCC (power), 135 GND (power), 143 VCC (power), 144 GND (power)

## M5LV-128/104-7VI
designator U?
High-Density and High-I/O Complex PLD
footprint TQFP144_N (Thin QFP, 144-Leads, Body 20x20mm, Pitch 0.5mm, IPC Medium Density)
footprint TQFP144_L (Thin QFP, 144-Leads, Body 20x20mm, Pitch 0.5mm, IPC High Density)
footprint TQFP144_M (Thin QFP, 144-Leads, Body 20x20mm, Pitch 0.5mm, IPC Low Density)
3D model M5LV-TQFP144 (144-Pin Thin Quad Flat Pack (TQFP144))
part A pins: 2 I/O0 0A14 (io), 3 I/O1 0B13 (io), 4 I/O2 0B12 (io), 5 I/O3 0B11 (io), 6 I/O4 0B10 (io), 8 I/O5 0B8 (io), 9 I/O6 0B7 (io), 10 I/O7 0B6 (io), 11 I/O8 0B5 (io), 13 I/O9 0B4 (io), 14 I/O10 0B3 (io), 15 I/O11 0B2 (io), 16 I/O12 0B1 (io), 21 I/O13 1B1 (io), 22 I/O14 1B2 (io), 23 I/O15 1B3 (io), 24 I/O16 1B4 (io), 26 I/O17 1B5 (io), 27 I/O18 1B6 (io), 28 I/O19 1B7 (io), 29 I/O20 1B8 (io), 31 I/O21 1B10 (io), 32 I/O22 1B11 (io), 33 I/O23 1B12 (io), 34 I/O24 1B13 (io), 35 I/O25 1A14 (io), 39 I/O26 1A13 (io), 40 I/O27 1A12 (io), 41 I/O28 1A11 (io), 42 I/O29 1A10 (io), 43 I/O30 1A8 (io), 44 I/O31 1A7 (io), 45 I/O32 1A6 (io), 47 I/O33 1A5 (io), 48 I/O34 1A4 (io), 49 I/O35 1A3 (io), 50 I/O36 1A2 (io), 51 I/O37 1A1 (io), 52 I/O38 1A0 (io), 57 I/O39 1D0 (io), 58 I/O40 1D1 (io), 59 I/O41 1D2 (io), 60 I/O42 1D3 (io), 61 I/O43 1D4 (io), 62 I/O44 1D5 (io), 64 I/O45 1D6 (io), 65 I/O46 1D7 (io), 66 I/O47 1D8 (io), 67 I/O48 1D10 (io), 68 I/O49 1D11 (io), 69 I/O50 1D12 (io), 70 I/O51 1D13 (io), 74 I/O52 1D14 (io), 75 I/O53 1C13 (io), 76 I/O54 1C12 (io), 77 I/O55 1C11 (io), 78 I/O56 1C10 (io), 80 I/O57 1C8 (io), 81 I/O58 1C7 (io), 82 I/O59 1C6 (io), 83 I/O60 1C5 (io), 85 I/O61 1C4 (io), 86 I/O62 1C3 (io), 87 I/O63 1C2 (io), 88 I/O64 1C1 (io), 93 I/O65 0C1 (io), 94 I/O66 0C2 (io), 95 I/O67 0C3 (io), 96 I/O68 0C4 (io), 98 I/O69 0C5 (io), 99 I/O70 0C6 (io), 100 I/O71 0C7 (io), 101 I/O72 0C8 (io), 103 I/O73 0C10 (io), 104 I/O74 0C11 (io), 105 I/O75 0C12 (io), 106 I/O76 0C13 (io), 107 I/O77 0D14 (io), 111 I/O78 0D13 (io), 112 I/O79 0D12 (io), 113 I/O80 0D11 (io), 114 I/O81 0D10 (io), 115 I/O82 0D8 (io), 116 I/O83 0D7 (io), 117 I/O84 0D6 (io), 119 I/O85 0D5 (io), 120 I/O86 0D4 (io), 121 I/O87 0D3 (io), 122 I/O88 0D2 (io), 123 I/O89 0D1 (io), 124 I/O90 0D0 (io), 129 I/O91 0A0 (io), 130 I/O92 0A1 (io), 131 I/O93 0A2 (io), 132 I/O94 0A3 (io), 133 I/O95 0A4 (io), 134 I/O96 0A5 (io), 136 I/O97 0A6 (io), 137 I/O98 0A7 (io), 138 I/O99 0A8 (io), 139 I/O100 0A10 (io), 140 I/O101 0A11 (io), 141 I/O102 0A12 (io), 142 I/O103 0A13 (io)
part B pins: 1 TDI (in), 7 GND (power), 12 GND (power), 17 I0/CLK0 (in), 18 VCC (power), 19 GND (power), 20 I1/CLK1 (in), 25 GND (power), 30 GND (power), 36 TCK (in), 37 GND (power), 38 VCC (power), 46 GND (power), 53 VCC (power), 54 GND (power), 55 GND (power), 56 VCC (power), 63 GND (power), 71 VCC (power), 72 GND (power), 73 TMS (in), 79 GND (power), 84 GND (power), 89 I2/CLK2 (in), 90 VCC (power), 91 GND (power), 92 I3/CLK3 (in), 97 GND (power), 102 GND (power), 108 TDO (out), 109 GND (power), 110 VCC (power), 118 GND (power), 125 VCC (power), 126 GND (power), 127 GND (power), 128 VCC (power), 135 GND (power), 143 VCC (power), 144 GND (power)

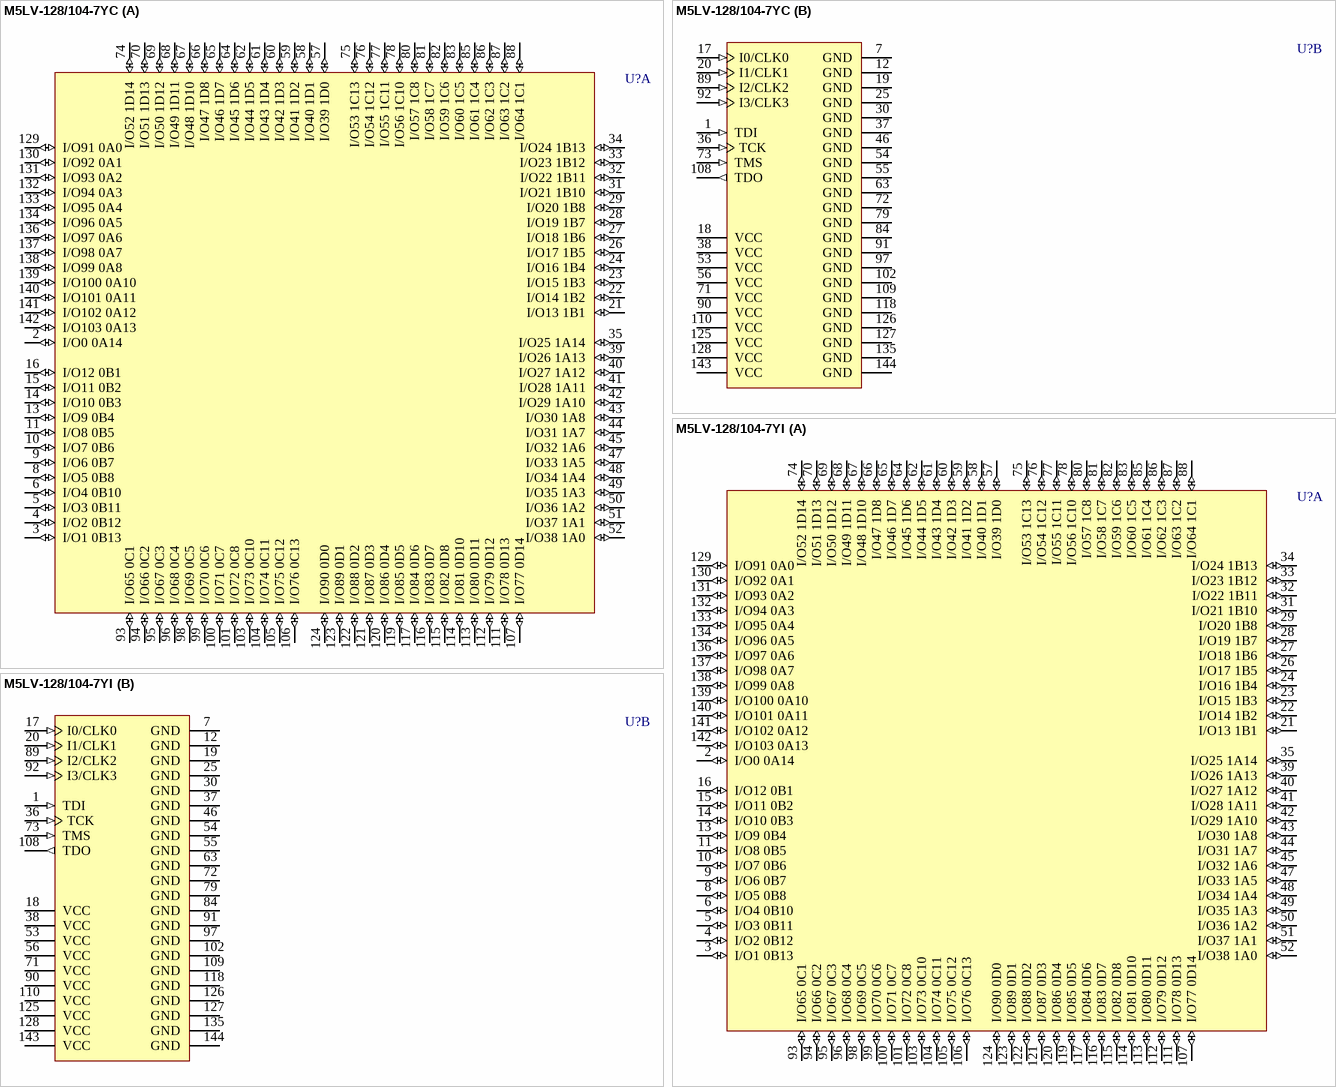
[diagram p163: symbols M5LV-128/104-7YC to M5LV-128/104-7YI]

## M5LV-128/104-7YC
designator U?
High-Density and High-I/O Complex PLD
footprint PQFP144_N (QFP, 144-Leads, Body 28 x 28mm, Pitch 0.65mm, IPC Medium Density)
footprint PQFP144_L (QFP, 144-Leads, Body 28 x 28mm, Pitch 0.65mm, IPC High Density)
footprint PQFP144_M (QFP, 144-Leads, Body 28 x 28mm, Pitch 0.65mm, IPC Low Density)
3D model M5LV-PQFP144 (144-Pin Quad Flat Pack 0.65 mm Pitch)
part A pins: 2 I/O0 0A14 (io), 3 I/O1 0B13 (io), 4 I/O2 0B12 (io), 5 I/O3 0B11 (io), 6 I/O4 0B10 (io), 8 I/O5 0B8 (io), 9 I/O6 0B7 (io), 10 I/O7 0B6 (io), 11 I/O8 0B5 (io), 13 I/O9 0B4 (io), 14 I/O10 0B3 (io), 15 I/O11 0B2 (io), 16 I/O12 0B1 (io), 21 I/O13 1B1 (io), 22 I/O14 1B2 (io), 23 I/O15 1B3 (io), 24 I/O16 1B4 (io), 26 I/O17 1B5 (io), 27 I/O18 1B6 (io), 28 I/O19 1B7 (io), 29 I/O20 1B8 (io), 31 I/O21 1B10 (io), 32 I/O22 1B11 (io), 33 I/O23 1B12 (io), 34 I/O24 1B13 (io), 35 I/O25 1A14 (io), 39 I/O26 1A13 (io), 40 I/O27 1A12 (io), 41 I/O28 1A11 (io), 42 I/O29 1A10 (io), 43 I/O30 1A8 (io), 44 I/O31 1A7 (io), 45 I/O32 1A6 (io), 47 I/O33 1A5 (io), 48 I/O34 1A4 (io), 49 I/O35 1A3 (io), 50 I/O36 1A2 (io), 51 I/O37 1A1 (io), 52 I/O38 1A0 (io), 57 I/O39 1D0 (io), 58 I/O40 1D1 (io), 59 I/O41 1D2 (io), 60 I/O42 1D3 (io), 61 I/O43 1D4 (io), 62 I/O44 1D5 (io), 64 I/O45 1D6 (io), 65 I/O46 1D7 (io), 66 I/O47 1D8 (io), 67 I/O48 1D10 (io), 68 I/O49 1D11 (io), 69 I/O50 1D12 (io), 70 I/O51 1D13 (io), 74 I/O52 1D14 (io), 75 I/O53 1C13 (io), 76 I/O54 1C12 (io), 77 I/O55 1C11 (io), 78 I/O56 1C10 (io), 80 I/O57 1C8 (io), 81 I/O58 1C7 (io), 82 I/O59 1C6 (io), 83 I/O60 1C5 (io), 85 I/O61 1C4 (io), 86 I/O62 1C3 (io), 87 I/O63 1C2 (io), 88 I/O64 1C1 (io), 93 I/O65 0C1 (io), 94 I/O66 0C2 (io), 95 I/O67 0C3 (io), 96 I/O68 0C4 (io), 98 I/O69 0C5 (io), 99 I/O70 0C6 (io), 100 I/O71 0C7 (io), 101 I/O72 0C8 (io), 103 I/O73 0C10 (io), 104 I/O74 0C11 (io), 105 I/O75 0C12 (io), 106 I/O76 0C13 (io), 107 I/O77 0D14 (io), 111 I/O78 0D13 (io), 112 I/O79 0D12 (io), 113 I/O80 0D11 (io), 114 I/O81 0D10 (io), 115 I/O82 0D8 (io), 116 I/O83 0D7 (io), 117 I/O84 0D6 (io), 119 I/O85 0D5 (io), 120 I/O86 0D4 (io), 121 I/O87 0D3 (io), 122 I/O88 0D2 (io), 123 I/O89 0D1 (io), 124 I/O90 0D0 (io), 129 I/O91 0A0 (io), 130 I/O92 0A1 (io), 131 I/O93 0A2 (io), 132 I/O94 0A3 (io), 133 I/O95 0A4 (io), 134 I/O96 0A5 (io), 136 I/O97 0A6 (io), 137 I/O98 0A7 (io), 138 I/O99 0A8 (io), 139 I/O100 0A10 (io), 140 I/O101 0A11 (io), 141 I/O102 0A12 (io), 142 I/O103 0A13 (io)
part B pins: 1 TDI (in), 7 GND (power), 12 GND (power), 17 I0/CLK0 (in), 18 VCC (power), 19 GND (power), 20 I1/CLK1 (in), 25 GND (power), 30 GND (power), 36 TCK (in), 37 GND (power), 38 VCC (power), 46 GND (power), 53 VCC (power), 54 GND (power), 55 GND (power), 56 VCC (power), 63 GND (power), 71 VCC (power), 72 GND (power), 73 TMS (in), 79 GND (power), 84 GND (power), 89 I2/CLK2 (in), 90 VCC (power), 91 GND (power), 92 I3/CLK3 (in), 97 GND (power), 102 GND (power), 108 TDO (out), 109 GND (power), 110 VCC (power), 118 GND (power), 125 VCC (power), 126 GND (power), 127 GND (power), 128 VCC (power), 135 GND (power), 143 VCC (power), 144 GND (power)

## M5LV-128/104-7YI
designator U?
High-Density and High-I/O Complex PLD
footprint PQFP144_N (QFP, 144-Leads, Body 28 x 28mm, Pitch 0.65mm, IPC Medium Density)
footprint PQFP144_L (QFP, 144-Leads, Body 28 x 28mm, Pitch 0.65mm, IPC High Density)
footprint PQFP144_M (QFP, 144-Leads, Body 28 x 28mm, Pitch 0.65mm, IPC Low Density)
3D model M5LV-PQFP144 (144-Pin Quad Flat Pack 0.65 mm Pitch)
part A pins: 2 I/O0 0A14 (io), 3 I/O1 0B13 (io), 4 I/O2 0B12 (io), 5 I/O3 0B11 (io), 6 I/O4 0B10 (io), 8 I/O5 0B8 (io), 9 I/O6 0B7 (io), 10 I/O7 0B6 (io), 11 I/O8 0B5 (io), 13 I/O9 0B4 (io), 14 I/O10 0B3 (io), 15 I/O11 0B2 (io), 16 I/O12 0B1 (io), 21 I/O13 1B1 (io), 22 I/O14 1B2 (io), 23 I/O15 1B3 (io), 24 I/O16 1B4 (io), 26 I/O17 1B5 (io), 27 I/O18 1B6 (io), 28 I/O19 1B7 (io), 29 I/O20 1B8 (io), 31 I/O21 1B10 (io), 32 I/O22 1B11 (io), 33 I/O23 1B12 (io), 34 I/O24 1B13 (io), 35 I/O25 1A14 (io), 39 I/O26 1A13 (io), 40 I/O27 1A12 (io), 41 I/O28 1A11 (io), 42 I/O29 1A10 (io), 43 I/O30 1A8 (io), 44 I/O31 1A7 (io), 45 I/O32 1A6 (io), 47 I/O33 1A5 (io), 48 I/O34 1A4 (io), 49 I/O35 1A3 (io), 50 I/O36 1A2 (io), 51 I/O37 1A1 (io), 52 I/O38 1A0 (io), 57 I/O39 1D0 (io), 58 I/O40 1D1 (io), 59 I/O41 1D2 (io), 60 I/O42 1D3 (io), 61 I/O43 1D4 (io), 62 I/O44 1D5 (io), 64 I/O45 1D6 (io), 65 I/O46 1D7 (io), 66 I/O47 1D8 (io), 67 I/O48 1D10 (io), 68 I/O49 1D11 (io), 69 I/O50 1D12 (io), 70 I/O51 1D13 (io), 74 I/O52 1D14 (io), 75 I/O53 1C13 (io), 76 I/O54 1C12 (io), 77 I/O55 1C11 (io), 78 I/O56 1C10 (io), 80 I/O57 1C8 (io), 81 I/O58 1C7 (io), 82 I/O59 1C6 (io), 83 I/O60 1C5 (io), 85 I/O61 1C4 (io), 86 I/O62 1C3 (io), 87 I/O63 1C2 (io), 88 I/O64 1C1 (io), 93 I/O65 0C1 (io), 94 I/O66 0C2 (io), 95 I/O67 0C3 (io), 96 I/O68 0C4 (io), 98 I/O69 0C5 (io), 99 I/O70 0C6 (io), 100 I/O71 0C7 (io), 101 I/O72 0C8 (io), 103 I/O73 0C10 (io), 104 I/O74 0C11 (io), 105 I/O75 0C12 (io), 106 I/O76 0C13 (io), 107 I/O77 0D14 (io), 111 I/O78 0D13 (io), 112 I/O79 0D12 (io), 113 I/O80 0D11 (io), 114 I/O81 0D10 (io), 115 I/O82 0D8 (io), 116 I/O83 0D7 (io), 117 I/O84 0D6 (io), 119 I/O85 0D5 (io), 120 I/O86 0D4 (io), 121 I/O87 0D3 (io), 122 I/O88 0D2 (io), 123 I/O89 0D1 (io), 124 I/O90 0D0 (io), 129 I/O91 0A0 (io), 130 I/O92 0A1 (io), 131 I/O93 0A2 (io), 132 I/O94 0A3 (io), 133 I/O95 0A4 (io), 134 I/O96 0A5 (io), 136 I/O97 0A6 (io), 137 I/O98 0A7 (io), 138 I/O99 0A8 (io), 139 I/O100 0A10 (io), 140 I/O101 0A11 (io), 141 I/O102 0A12 (io), 142 I/O103 0A13 (io)
part B pins: 1 TDI (in), 7 GND (power), 12 GND (power), 17 I0/CLK0 (in), 18 VCC (power), 19 GND (power), 20 I1/CLK1 (in), 25 GND (power), 30 GND (power), 36 TCK (in), 37 GND (power), 38 VCC (power), 46 GND (power), 53 VCC (power), 54 GND (power), 55 GND (power), 56 VCC (power), 63 GND (power), 71 VCC (power), 72 GND (power), 73 TMS (in), 79 GND (power), 84 GND (power), 89 I2/CLK2 (in), 90 VCC (power), 91 GND (power), 92 I3/CLK3 (in), 97 GND (power), 102 GND (power), 108 TDO (out), 109 GND (power), 110 VCC (power), 118 GND (power), 125 VCC (power), 126 GND (power), 127 GND (power), 128 VCC (power), 135 GND (power), 143 VCC (power), 144 GND (power)

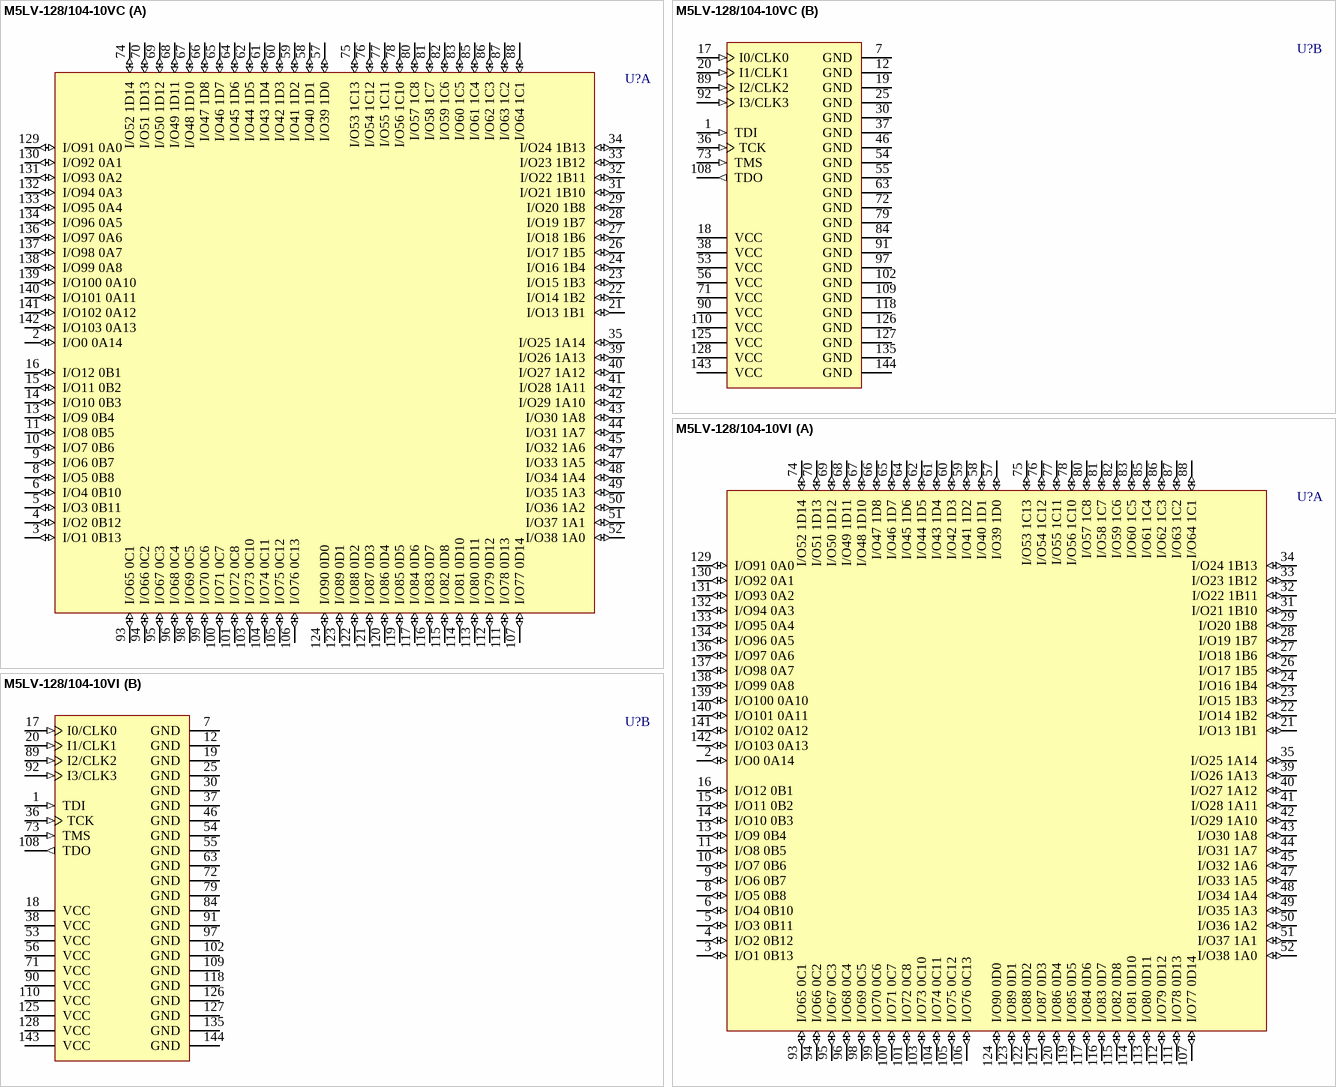
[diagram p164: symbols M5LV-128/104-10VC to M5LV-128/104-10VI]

## M5LV-128/104-10VC
designator U?
High-Density and High-I/O Complex PLD
footprint TQFP144_N (Thin QFP, 144-Leads, Body 20x20mm, Pitch 0.5mm, IPC Medium Density)
footprint TQFP144_L (Thin QFP, 144-Leads, Body 20x20mm, Pitch 0.5mm, IPC High Density)
footprint TQFP144_M (Thin QFP, 144-Leads, Body 20x20mm, Pitch 0.5mm, IPC Low Density)
3D model M5LV-TQFP144 (144-Pin Thin Quad Flat Pack (TQFP144))
part A pins: 2 I/O0 0A14 (io), 3 I/O1 0B13 (io), 4 I/O2 0B12 (io), 5 I/O3 0B11 (io), 6 I/O4 0B10 (io), 8 I/O5 0B8 (io), 9 I/O6 0B7 (io), 10 I/O7 0B6 (io), 11 I/O8 0B5 (io), 13 I/O9 0B4 (io), 14 I/O10 0B3 (io), 15 I/O11 0B2 (io), 16 I/O12 0B1 (io), 21 I/O13 1B1 (io), 22 I/O14 1B2 (io), 23 I/O15 1B3 (io), 24 I/O16 1B4 (io), 26 I/O17 1B5 (io), 27 I/O18 1B6 (io), 28 I/O19 1B7 (io), 29 I/O20 1B8 (io), 31 I/O21 1B10 (io), 32 I/O22 1B11 (io), 33 I/O23 1B12 (io), 34 I/O24 1B13 (io), 35 I/O25 1A14 (io), 39 I/O26 1A13 (io), 40 I/O27 1A12 (io), 41 I/O28 1A11 (io), 42 I/O29 1A10 (io), 43 I/O30 1A8 (io), 44 I/O31 1A7 (io), 45 I/O32 1A6 (io), 47 I/O33 1A5 (io), 48 I/O34 1A4 (io), 49 I/O35 1A3 (io), 50 I/O36 1A2 (io), 51 I/O37 1A1 (io), 52 I/O38 1A0 (io), 57 I/O39 1D0 (io), 58 I/O40 1D1 (io), 59 I/O41 1D2 (io), 60 I/O42 1D3 (io), 61 I/O43 1D4 (io), 62 I/O44 1D5 (io), 64 I/O45 1D6 (io), 65 I/O46 1D7 (io), 66 I/O47 1D8 (io), 67 I/O48 1D10 (io), 68 I/O49 1D11 (io), 69 I/O50 1D12 (io), 70 I/O51 1D13 (io), 74 I/O52 1D14 (io), 75 I/O53 1C13 (io), 76 I/O54 1C12 (io), 77 I/O55 1C11 (io), 78 I/O56 1C10 (io), 80 I/O57 1C8 (io), 81 I/O58 1C7 (io), 82 I/O59 1C6 (io), 83 I/O60 1C5 (io), 85 I/O61 1C4 (io), 86 I/O62 1C3 (io), 87 I/O63 1C2 (io), 88 I/O64 1C1 (io), 93 I/O65 0C1 (io), 94 I/O66 0C2 (io), 95 I/O67 0C3 (io), 96 I/O68 0C4 (io), 98 I/O69 0C5 (io), 99 I/O70 0C6 (io), 100 I/O71 0C7 (io), 101 I/O72 0C8 (io), 103 I/O73 0C10 (io), 104 I/O74 0C11 (io), 105 I/O75 0C12 (io), 106 I/O76 0C13 (io), 107 I/O77 0D14 (io), 111 I/O78 0D13 (io), 112 I/O79 0D12 (io), 113 I/O80 0D11 (io), 114 I/O81 0D10 (io), 115 I/O82 0D8 (io), 116 I/O83 0D7 (io), 117 I/O84 0D6 (io), 119 I/O85 0D5 (io), 120 I/O86 0D4 (io), 121 I/O87 0D3 (io), 122 I/O88 0D2 (io), 123 I/O89 0D1 (io), 124 I/O90 0D0 (io), 129 I/O91 0A0 (io), 130 I/O92 0A1 (io), 131 I/O93 0A2 (io), 132 I/O94 0A3 (io), 133 I/O95 0A4 (io), 134 I/O96 0A5 (io), 136 I/O97 0A6 (io), 137 I/O98 0A7 (io), 138 I/O99 0A8 (io), 139 I/O100 0A10 (io), 140 I/O101 0A11 (io), 141 I/O102 0A12 (io), 142 I/O103 0A13 (io)
part B pins: 1 TDI (in), 7 GND (power), 12 GND (power), 17 I0/CLK0 (in), 18 VCC (power), 19 GND (power), 20 I1/CLK1 (in), 25 GND (power), 30 GND (power), 36 TCK (in), 37 GND (power), 38 VCC (power), 46 GND (power), 53 VCC (power), 54 GND (power), 55 GND (power), 56 VCC (power), 63 GND (power), 71 VCC (power), 72 GND (power), 73 TMS (in), 79 GND (power), 84 GND (power), 89 I2/CLK2 (in), 90 VCC (power), 91 GND (power), 92 I3/CLK3 (in), 97 GND (power), 102 GND (power), 108 TDO (out), 109 GND (power), 110 VCC (power), 118 GND (power), 125 VCC (power), 126 GND (power), 127 GND (power), 128 VCC (power), 135 GND (power), 143 VCC (power), 144 GND (power)

## M5LV-128/104-10VI
designator U?
High-Density and High-I/O Complex PLD
footprint TQFP144_N (Thin QFP, 144-Leads, Body 20x20mm, Pitch 0.5mm, IPC Medium Density)
footprint TQFP144_L (Thin QFP, 144-Leads, Body 20x20mm, Pitch 0.5mm, IPC High Density)
footprint TQFP144_M (Thin QFP, 144-Leads, Body 20x20mm, Pitch 0.5mm, IPC Low Density)
3D model M5LV-TQFP144 (144-Pin Thin Quad Flat Pack (TQFP144))
part A pins: 2 I/O0 0A14 (io), 3 I/O1 0B13 (io), 4 I/O2 0B12 (io), 5 I/O3 0B11 (io), 6 I/O4 0B10 (io), 8 I/O5 0B8 (io), 9 I/O6 0B7 (io), 10 I/O7 0B6 (io), 11 I/O8 0B5 (io), 13 I/O9 0B4 (io), 14 I/O10 0B3 (io), 15 I/O11 0B2 (io), 16 I/O12 0B1 (io), 21 I/O13 1B1 (io), 22 I/O14 1B2 (io), 23 I/O15 1B3 (io), 24 I/O16 1B4 (io), 26 I/O17 1B5 (io), 27 I/O18 1B6 (io), 28 I/O19 1B7 (io), 29 I/O20 1B8 (io), 31 I/O21 1B10 (io), 32 I/O22 1B11 (io), 33 I/O23 1B12 (io), 34 I/O24 1B13 (io), 35 I/O25 1A14 (io), 39 I/O26 1A13 (io), 40 I/O27 1A12 (io), 41 I/O28 1A11 (io), 42 I/O29 1A10 (io), 43 I/O30 1A8 (io), 44 I/O31 1A7 (io), 45 I/O32 1A6 (io), 47 I/O33 1A5 (io), 48 I/O34 1A4 (io), 49 I/O35 1A3 (io), 50 I/O36 1A2 (io), 51 I/O37 1A1 (io), 52 I/O38 1A0 (io), 57 I/O39 1D0 (io), 58 I/O40 1D1 (io), 59 I/O41 1D2 (io), 60 I/O42 1D3 (io), 61 I/O43 1D4 (io), 62 I/O44 1D5 (io), 64 I/O45 1D6 (io), 65 I/O46 1D7 (io), 66 I/O47 1D8 (io), 67 I/O48 1D10 (io), 68 I/O49 1D11 (io), 69 I/O50 1D12 (io), 70 I/O51 1D13 (io), 74 I/O52 1D14 (io), 75 I/O53 1C13 (io), 76 I/O54 1C12 (io), 77 I/O55 1C11 (io), 78 I/O56 1C10 (io), 80 I/O57 1C8 (io), 81 I/O58 1C7 (io), 82 I/O59 1C6 (io), 83 I/O60 1C5 (io), 85 I/O61 1C4 (io), 86 I/O62 1C3 (io), 87 I/O63 1C2 (io), 88 I/O64 1C1 (io), 93 I/O65 0C1 (io), 94 I/O66 0C2 (io), 95 I/O67 0C3 (io), 96 I/O68 0C4 (io), 98 I/O69 0C5 (io), 99 I/O70 0C6 (io), 100 I/O71 0C7 (io), 101 I/O72 0C8 (io), 103 I/O73 0C10 (io), 104 I/O74 0C11 (io), 105 I/O75 0C12 (io), 106 I/O76 0C13 (io), 107 I/O77 0D14 (io), 111 I/O78 0D13 (io), 112 I/O79 0D12 (io), 113 I/O80 0D11 (io), 114 I/O81 0D10 (io), 115 I/O82 0D8 (io), 116 I/O83 0D7 (io), 117 I/O84 0D6 (io), 119 I/O85 0D5 (io), 120 I/O86 0D4 (io), 121 I/O87 0D3 (io), 122 I/O88 0D2 (io), 123 I/O89 0D1 (io), 124 I/O90 0D0 (io), 129 I/O91 0A0 (io), 130 I/O92 0A1 (io), 131 I/O93 0A2 (io), 132 I/O94 0A3 (io), 133 I/O95 0A4 (io), 134 I/O96 0A5 (io), 136 I/O97 0A6 (io), 137 I/O98 0A7 (io), 138 I/O99 0A8 (io), 139 I/O100 0A10 (io), 140 I/O101 0A11 (io), 141 I/O102 0A12 (io), 142 I/O103 0A13 (io)
part B pins: 1 TDI (in), 7 GND (power), 12 GND (power), 17 I0/CLK0 (in), 18 VCC (power), 19 GND (power), 20 I1/CLK1 (in), 25 GND (power), 30 GND (power), 36 TCK (in), 37 GND (power), 38 VCC (power), 46 GND (power), 53 VCC (power), 54 GND (power), 55 GND (power), 56 VCC (power), 63 GND (power), 71 VCC (power), 72 GND (power), 73 TMS (in), 79 GND (power), 84 GND (power), 89 I2/CLK2 (in), 90 VCC (power), 91 GND (power), 92 I3/CLK3 (in), 97 GND (power), 102 GND (power), 108 TDO (out), 109 GND (power), 110 VCC (power), 118 GND (power), 125 VCC (power), 126 GND (power), 127 GND (power), 128 VCC (power), 135 GND (power), 143 VCC (power), 144 GND (power)

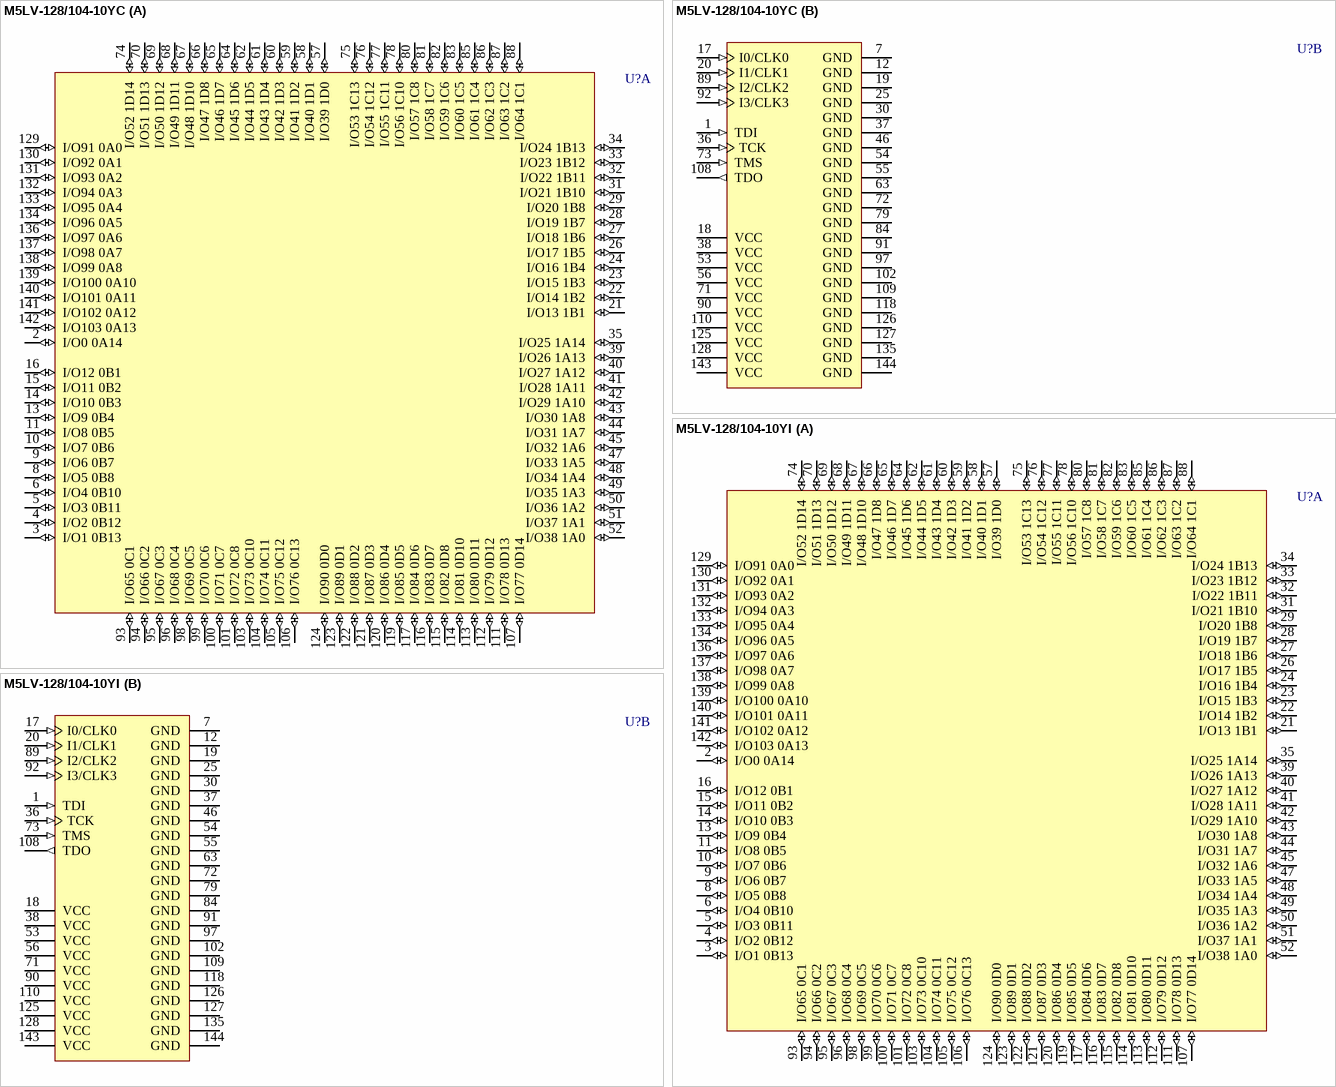
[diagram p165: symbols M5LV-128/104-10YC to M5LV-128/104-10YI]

## M5LV-128/104-10YC
designator U?
High-Density and High-I/O Complex PLD
footprint PQFP144_N (QFP, 144-Leads, Body 28 x 28mm, Pitch 0.65mm, IPC Medium Density)
footprint PQFP144_L (QFP, 144-Leads, Body 28 x 28mm, Pitch 0.65mm, IPC High Density)
footprint PQFP144_M (QFP, 144-Leads, Body 28 x 28mm, Pitch 0.65mm, IPC Low Density)
3D model M5LV-PQFP144 (144-Pin Quad Flat Pack 0.65 mm Pitch)
part A pins: 2 I/O0 0A14 (io), 3 I/O1 0B13 (io), 4 I/O2 0B12 (io), 5 I/O3 0B11 (io), 6 I/O4 0B10 (io), 8 I/O5 0B8 (io), 9 I/O6 0B7 (io), 10 I/O7 0B6 (io), 11 I/O8 0B5 (io), 13 I/O9 0B4 (io), 14 I/O10 0B3 (io), 15 I/O11 0B2 (io), 16 I/O12 0B1 (io), 21 I/O13 1B1 (io), 22 I/O14 1B2 (io), 23 I/O15 1B3 (io), 24 I/O16 1B4 (io), 26 I/O17 1B5 (io), 27 I/O18 1B6 (io), 28 I/O19 1B7 (io), 29 I/O20 1B8 (io), 31 I/O21 1B10 (io), 32 I/O22 1B11 (io), 33 I/O23 1B12 (io), 34 I/O24 1B13 (io), 35 I/O25 1A14 (io), 39 I/O26 1A13 (io), 40 I/O27 1A12 (io), 41 I/O28 1A11 (io), 42 I/O29 1A10 (io), 43 I/O30 1A8 (io), 44 I/O31 1A7 (io), 45 I/O32 1A6 (io), 47 I/O33 1A5 (io), 48 I/O34 1A4 (io), 49 I/O35 1A3 (io), 50 I/O36 1A2 (io), 51 I/O37 1A1 (io), 52 I/O38 1A0 (io), 57 I/O39 1D0 (io), 58 I/O40 1D1 (io), 59 I/O41 1D2 (io), 60 I/O42 1D3 (io), 61 I/O43 1D4 (io), 62 I/O44 1D5 (io), 64 I/O45 1D6 (io), 65 I/O46 1D7 (io), 66 I/O47 1D8 (io), 67 I/O48 1D10 (io), 68 I/O49 1D11 (io), 69 I/O50 1D12 (io), 70 I/O51 1D13 (io), 74 I/O52 1D14 (io), 75 I/O53 1C13 (io), 76 I/O54 1C12 (io), 77 I/O55 1C11 (io), 78 I/O56 1C10 (io), 80 I/O57 1C8 (io), 81 I/O58 1C7 (io), 82 I/O59 1C6 (io), 83 I/O60 1C5 (io), 85 I/O61 1C4 (io), 86 I/O62 1C3 (io), 87 I/O63 1C2 (io), 88 I/O64 1C1 (io), 93 I/O65 0C1 (io), 94 I/O66 0C2 (io), 95 I/O67 0C3 (io), 96 I/O68 0C4 (io), 98 I/O69 0C5 (io), 99 I/O70 0C6 (io), 100 I/O71 0C7 (io), 101 I/O72 0C8 (io), 103 I/O73 0C10 (io), 104 I/O74 0C11 (io), 105 I/O75 0C12 (io), 106 I/O76 0C13 (io), 107 I/O77 0D14 (io), 111 I/O78 0D13 (io), 112 I/O79 0D12 (io), 113 I/O80 0D11 (io), 114 I/O81 0D10 (io), 115 I/O82 0D8 (io), 116 I/O83 0D7 (io), 117 I/O84 0D6 (io), 119 I/O85 0D5 (io), 120 I/O86 0D4 (io), 121 I/O87 0D3 (io), 122 I/O88 0D2 (io), 123 I/O89 0D1 (io), 124 I/O90 0D0 (io), 129 I/O91 0A0 (io), 130 I/O92 0A1 (io), 131 I/O93 0A2 (io), 132 I/O94 0A3 (io), 133 I/O95 0A4 (io), 134 I/O96 0A5 (io), 136 I/O97 0A6 (io), 137 I/O98 0A7 (io), 138 I/O99 0A8 (io), 139 I/O100 0A10 (io), 140 I/O101 0A11 (io), 141 I/O102 0A12 (io), 142 I/O103 0A13 (io)
part B pins: 1 TDI (in), 7 GND (power), 12 GND (power), 17 I0/CLK0 (in), 18 VCC (power), 19 GND (power), 20 I1/CLK1 (in), 25 GND (power), 30 GND (power), 36 TCK (in), 37 GND (power), 38 VCC (power), 46 GND (power), 53 VCC (power), 54 GND (power), 55 GND (power), 56 VCC (power), 63 GND (power), 71 VCC (power), 72 GND (power), 73 TMS (in), 79 GND (power), 84 GND (power), 89 I2/CLK2 (in), 90 VCC (power), 91 GND (power), 92 I3/CLK3 (in), 97 GND (power), 102 GND (power), 108 TDO (out), 109 GND (power), 110 VCC (power), 118 GND (power), 125 VCC (power), 126 GND (power), 127 GND (power), 128 VCC (power), 135 GND (power), 143 VCC (power), 144 GND (power)

## M5LV-128/104-10YI
designator U?
High-Density and High-I/O Complex PLD
footprint PQFP144_N (QFP, 144-Leads, Body 28 x 28mm, Pitch 0.65mm, IPC Medium Density)
footprint PQFP144_L (QFP, 144-Leads, Body 28 x 28mm, Pitch 0.65mm, IPC High Density)
footprint PQFP144_M (QFP, 144-Leads, Body 28 x 28mm, Pitch 0.65mm, IPC Low Density)
3D model M5LV-PQFP144 (144-Pin Quad Flat Pack 0.65 mm Pitch)
part A pins: 2 I/O0 0A14 (io), 3 I/O1 0B13 (io), 4 I/O2 0B12 (io), 5 I/O3 0B11 (io), 6 I/O4 0B10 (io), 8 I/O5 0B8 (io), 9 I/O6 0B7 (io), 10 I/O7 0B6 (io), 11 I/O8 0B5 (io), 13 I/O9 0B4 (io), 14 I/O10 0B3 (io), 15 I/O11 0B2 (io), 16 I/O12 0B1 (io), 21 I/O13 1B1 (io), 22 I/O14 1B2 (io), 23 I/O15 1B3 (io), 24 I/O16 1B4 (io), 26 I/O17 1B5 (io), 27 I/O18 1B6 (io), 28 I/O19 1B7 (io), 29 I/O20 1B8 (io), 31 I/O21 1B10 (io), 32 I/O22 1B11 (io), 33 I/O23 1B12 (io), 34 I/O24 1B13 (io), 35 I/O25 1A14 (io), 39 I/O26 1A13 (io), 40 I/O27 1A12 (io), 41 I/O28 1A11 (io), 42 I/O29 1A10 (io), 43 I/O30 1A8 (io), 44 I/O31 1A7 (io), 45 I/O32 1A6 (io), 47 I/O33 1A5 (io), 48 I/O34 1A4 (io), 49 I/O35 1A3 (io), 50 I/O36 1A2 (io), 51 I/O37 1A1 (io), 52 I/O38 1A0 (io), 57 I/O39 1D0 (io), 58 I/O40 1D1 (io), 59 I/O41 1D2 (io), 60 I/O42 1D3 (io), 61 I/O43 1D4 (io), 62 I/O44 1D5 (io), 64 I/O45 1D6 (io), 65 I/O46 1D7 (io), 66 I/O47 1D8 (io), 67 I/O48 1D10 (io), 68 I/O49 1D11 (io), 69 I/O50 1D12 (io), 70 I/O51 1D13 (io), 74 I/O52 1D14 (io), 75 I/O53 1C13 (io), 76 I/O54 1C12 (io), 77 I/O55 1C11 (io), 78 I/O56 1C10 (io), 80 I/O57 1C8 (io), 81 I/O58 1C7 (io), 82 I/O59 1C6 (io), 83 I/O60 1C5 (io), 85 I/O61 1C4 (io), 86 I/O62 1C3 (io), 87 I/O63 1C2 (io), 88 I/O64 1C1 (io), 93 I/O65 0C1 (io), 94 I/O66 0C2 (io), 95 I/O67 0C3 (io), 96 I/O68 0C4 (io), 98 I/O69 0C5 (io), 99 I/O70 0C6 (io), 100 I/O71 0C7 (io), 101 I/O72 0C8 (io), 103 I/O73 0C10 (io), 104 I/O74 0C11 (io), 105 I/O75 0C12 (io), 106 I/O76 0C13 (io), 107 I/O77 0D14 (io), 111 I/O78 0D13 (io), 112 I/O79 0D12 (io), 113 I/O80 0D11 (io), 114 I/O81 0D10 (io), 115 I/O82 0D8 (io), 116 I/O83 0D7 (io), 117 I/O84 0D6 (io), 119 I/O85 0D5 (io), 120 I/O86 0D4 (io), 121 I/O87 0D3 (io), 122 I/O88 0D2 (io), 123 I/O89 0D1 (io), 124 I/O90 0D0 (io), 129 I/O91 0A0 (io), 130 I/O92 0A1 (io), 131 I/O93 0A2 (io), 132 I/O94 0A3 (io), 133 I/O95 0A4 (io), 134 I/O96 0A5 (io), 136 I/O97 0A6 (io), 137 I/O98 0A7 (io), 138 I/O99 0A8 (io), 139 I/O100 0A10 (io), 140 I/O101 0A11 (io), 141 I/O102 0A12 (io), 142 I/O103 0A13 (io)
part B pins: 1 TDI (in), 7 GND (power), 12 GND (power), 17 I0/CLK0 (in), 18 VCC (power), 19 GND (power), 20 I1/CLK1 (in), 25 GND (power), 30 GND (power), 36 TCK (in), 37 GND (power), 38 VCC (power), 46 GND (power), 53 VCC (power), 54 GND (power), 55 GND (power), 56 VCC (power), 63 GND (power), 71 VCC (power), 72 GND (power), 73 TMS (in), 79 GND (power), 84 GND (power), 89 I2/CLK2 (in), 90 VCC (power), 91 GND (power), 92 I3/CLK3 (in), 97 GND (power), 102 GND (power), 108 TDO (out), 109 GND (power), 110 VCC (power), 118 GND (power), 125 VCC (power), 126 GND (power), 127 GND (power), 128 VCC (power), 135 GND (power), 143 VCC (power), 144 GND (power)

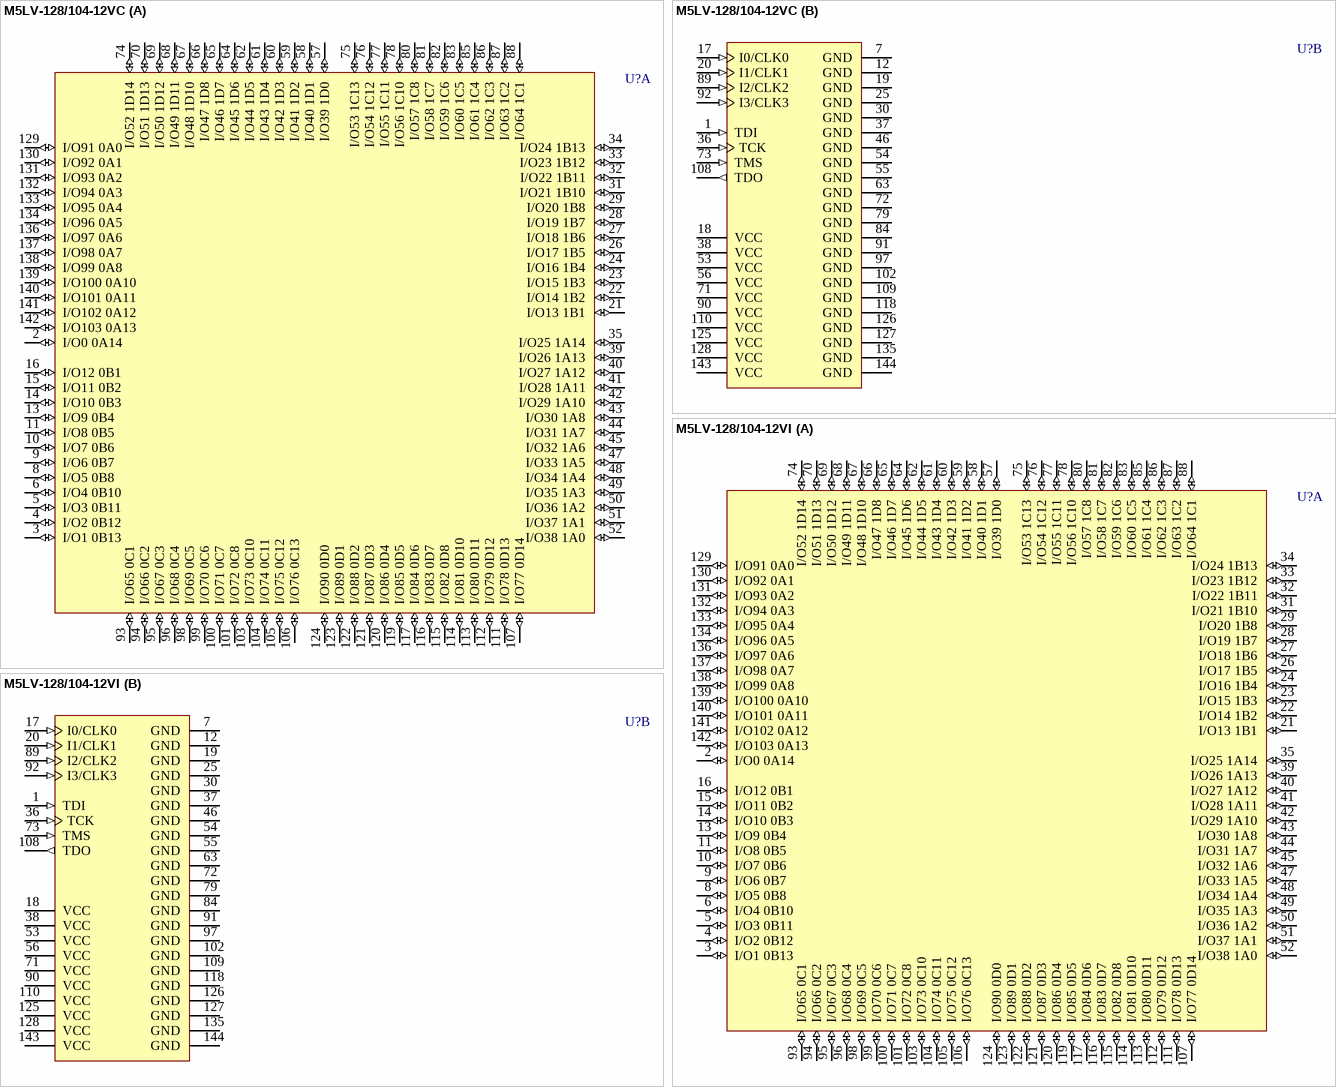
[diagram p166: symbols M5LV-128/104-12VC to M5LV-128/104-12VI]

## M5LV-128/104-12VC
designator U?
High-Density and High-I/O Complex PLD
footprint TQFP144_N (Thin QFP, 144-Leads, Body 20x20mm, Pitch 0.5mm, IPC Medium Density)
footprint TQFP144_L (Thin QFP, 144-Leads, Body 20x20mm, Pitch 0.5mm, IPC High Density)
footprint TQFP144_M (Thin QFP, 144-Leads, Body 20x20mm, Pitch 0.5mm, IPC Low Density)
3D model M5LV-TQFP144 (144-Pin Thin Quad Flat Pack (TQFP144))
part A pins: 2 I/O0 0A14 (io), 3 I/O1 0B13 (io), 4 I/O2 0B12 (io), 5 I/O3 0B11 (io), 6 I/O4 0B10 (io), 8 I/O5 0B8 (io), 9 I/O6 0B7 (io), 10 I/O7 0B6 (io), 11 I/O8 0B5 (io), 13 I/O9 0B4 (io), 14 I/O10 0B3 (io), 15 I/O11 0B2 (io), 16 I/O12 0B1 (io), 21 I/O13 1B1 (io), 22 I/O14 1B2 (io), 23 I/O15 1B3 (io), 24 I/O16 1B4 (io), 26 I/O17 1B5 (io), 27 I/O18 1B6 (io), 28 I/O19 1B7 (io), 29 I/O20 1B8 (io), 31 I/O21 1B10 (io), 32 I/O22 1B11 (io), 33 I/O23 1B12 (io), 34 I/O24 1B13 (io), 35 I/O25 1A14 (io), 39 I/O26 1A13 (io), 40 I/O27 1A12 (io), 41 I/O28 1A11 (io), 42 I/O29 1A10 (io), 43 I/O30 1A8 (io), 44 I/O31 1A7 (io), 45 I/O32 1A6 (io), 47 I/O33 1A5 (io), 48 I/O34 1A4 (io), 49 I/O35 1A3 (io), 50 I/O36 1A2 (io), 51 I/O37 1A1 (io), 52 I/O38 1A0 (io), 57 I/O39 1D0 (io), 58 I/O40 1D1 (io), 59 I/O41 1D2 (io), 60 I/O42 1D3 (io), 61 I/O43 1D4 (io), 62 I/O44 1D5 (io), 64 I/O45 1D6 (io), 65 I/O46 1D7 (io), 66 I/O47 1D8 (io), 67 I/O48 1D10 (io), 68 I/O49 1D11 (io), 69 I/O50 1D12 (io), 70 I/O51 1D13 (io), 74 I/O52 1D14 (io), 75 I/O53 1C13 (io), 76 I/O54 1C12 (io), 77 I/O55 1C11 (io), 78 I/O56 1C10 (io), 80 I/O57 1C8 (io), 81 I/O58 1C7 (io), 82 I/O59 1C6 (io), 83 I/O60 1C5 (io), 85 I/O61 1C4 (io), 86 I/O62 1C3 (io), 87 I/O63 1C2 (io), 88 I/O64 1C1 (io), 93 I/O65 0C1 (io), 94 I/O66 0C2 (io), 95 I/O67 0C3 (io), 96 I/O68 0C4 (io), 98 I/O69 0C5 (io), 99 I/O70 0C6 (io), 100 I/O71 0C7 (io), 101 I/O72 0C8 (io), 103 I/O73 0C10 (io), 104 I/O74 0C11 (io), 105 I/O75 0C12 (io), 106 I/O76 0C13 (io), 107 I/O77 0D14 (io), 111 I/O78 0D13 (io), 112 I/O79 0D12 (io), 113 I/O80 0D11 (io), 114 I/O81 0D10 (io), 115 I/O82 0D8 (io), 116 I/O83 0D7 (io), 117 I/O84 0D6 (io), 119 I/O85 0D5 (io), 120 I/O86 0D4 (io), 121 I/O87 0D3 (io), 122 I/O88 0D2 (io), 123 I/O89 0D1 (io), 124 I/O90 0D0 (io), 129 I/O91 0A0 (io), 130 I/O92 0A1 (io), 131 I/O93 0A2 (io), 132 I/O94 0A3 (io), 133 I/O95 0A4 (io), 134 I/O96 0A5 (io), 136 I/O97 0A6 (io), 137 I/O98 0A7 (io), 138 I/O99 0A8 (io), 139 I/O100 0A10 (io), 140 I/O101 0A11 (io), 141 I/O102 0A12 (io), 142 I/O103 0A13 (io)
part B pins: 1 TDI (in), 7 GND (power), 12 GND (power), 17 I0/CLK0 (in), 18 VCC (power), 19 GND (power), 20 I1/CLK1 (in), 25 GND (power), 30 GND (power), 36 TCK (in), 37 GND (power), 38 VCC (power), 46 GND (power), 53 VCC (power), 54 GND (power), 55 GND (power), 56 VCC (power), 63 GND (power), 71 VCC (power), 72 GND (power), 73 TMS (in), 79 GND (power), 84 GND (power), 89 I2/CLK2 (in), 90 VCC (power), 91 GND (power), 92 I3/CLK3 (in), 97 GND (power), 102 GND (power), 108 TDO (out), 109 GND (power), 110 VCC (power), 118 GND (power), 125 VCC (power), 126 GND (power), 127 GND (power), 128 VCC (power), 135 GND (power), 143 VCC (power), 144 GND (power)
